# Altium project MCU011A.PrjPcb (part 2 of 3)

## Sheet MCU011A_EMCInputFilter.SchDoc: EMC Input Filter
size 431 x 279 mm; Date: Not shown in title block; ApprovedBy: Not shown in title block; CheckedBy: Not shown in title block; Author: Not shown in title block; CompanyName: Not shown in title block; Engineer: Not shown in title block; Organization: Not shown in title block; Address1: Not shown in title block; Address2: Not shown in title block; Address3: Not shown in title block; Address4: Not shown in title block; DocumentNumber: 1; Revision: Use project parameter SCH_Rev; SheetNumber: 2; SheetTotal: 10; PageSetup: Record=PageOptions¦CenterHorizontal=True¦CenterVertical=True¦PrintScale=1.00¦XCorrection=1.00¦YCorrection=1.00¦PrintKind=0¦BorderSize=5000000¦LeftOffset=0¦BottomOffset=0¦Orientation=2¦PaperLength=1000¦PaperWidth=1000¦Scale=100¦PaperSource=15¦PrintQuality=600¦MediaType=1¦DitherType=10¦PaperKind=Letter¦PrintScaleMode=1
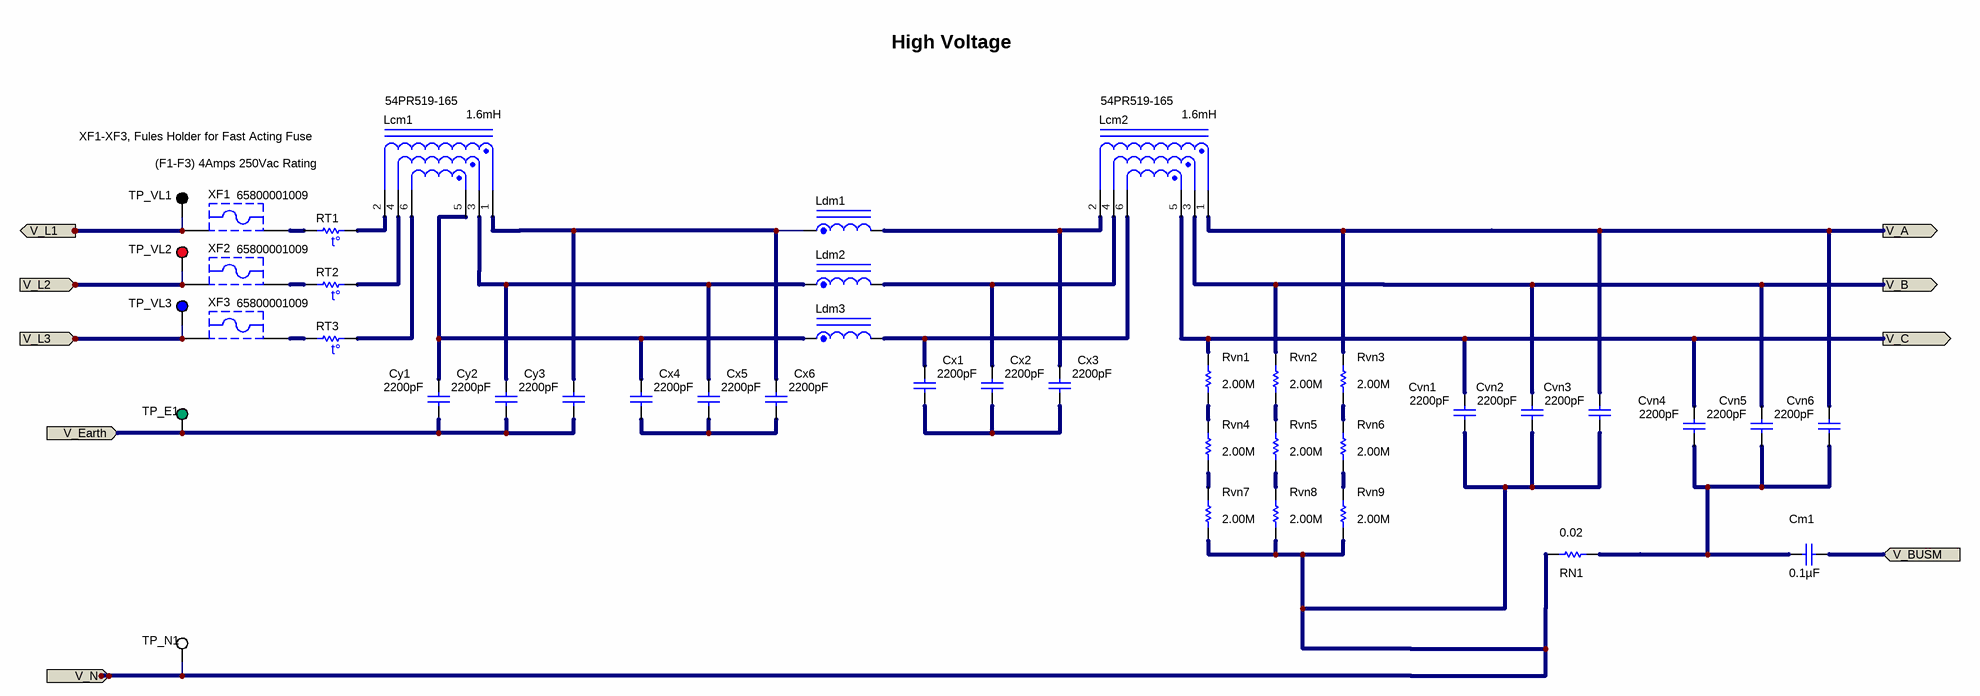
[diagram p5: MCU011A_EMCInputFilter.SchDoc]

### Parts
Cm1  ValueDisplayed: 0.1µF  [CAPRR1500W60L1750T550H1250]  (hidden comment: ECQ-U2A104ML)
Cvn1  ValueDisplayed: 2200pF  [2220_280]  (hidden comment: GA355QR7GF222KW01L)
Cvn2  ValueDisplayed: 2200pF  [2220_280]  (hidden comment: GA355QR7GF222KW01L)
Cvn3  ValueDisplayed: 2200pF  [2220_280]  (hidden comment: GA355QR7GF222KW01L)
Cvn4  ValueDisplayed: 2200pF  [2220_280]  (hidden comment: GA355QR7GF222KW01L)
Cvn5  ValueDisplayed: 2200pF  [2220_280]  (hidden comment: GA355QR7GF222KW01L)
Cvn6  ValueDisplayed: 2200pF  [2220_280]  (hidden comment: GA355QR7GF222KW01L)
Cx1  ValueDisplayed: 2200pF  [2220_280]  (hidden comment: GA355QR7GF222KW01L)
Cx2  ValueDisplayed: 2200pF  [2220_280]  (hidden comment: GA355QR7GF222KW01L)
Cx3  ValueDisplayed: 2200pF  [2220_280]  (hidden comment: GA355QR7GF222KW01L)
Cx4  ValueDisplayed: 2200pF  [2220_280]  (hidden comment: GA355QR7GF222KW01L)
Cx5  ValueDisplayed: 2200pF  [2220_280]  (hidden comment: GA355QR7GF222KW01L)
Cx6  ValueDisplayed: 2200pF  [2220_280]  (hidden comment: GA355QR7GF222KW01L)
Cy1  ValueDisplayed: 2200pF  [2220_280]  (hidden comment: GA355QR7GF222KW01L)
Cy2  ValueDisplayed: 2200pF  [2220_280]  (hidden comment: GA355QR7GF222KW01L)
Cy3  ValueDisplayed: 2200pF  [2220_280]  (hidden comment: GA355QR7GF222KW01L)
Lcm1  54PR519-165  ValueDisplayed: 1.6mH  [54PR519]
Lcm2  54PR519-165  ValueDisplayed: 1.6mH  [54PR519]
Ldm1  PA0431LNL  [PA0431LNL]  (value not drawn)
Ldm2  PA0431LNL  [PA0431LNL]  (value not drawn)
Ldm3  PA0431LNL  [PA0431LNL]  (value not drawn)
RN1  ValueDisplayed: 0.02  [2512]  (hidden comment: CRA2512-FZ-R020ELF)
RT1  SL32 10015  [AMETHERM_SL32]  (value not drawn)
RT2  SL32 10015  [AMETHERM_SL32]  (value not drawn)
RT3  SL32 10015  [AMETHERM_SL32]  (value not drawn)
Rvn1  ValueDisplayed: 2.00M  [0805_HV]  (hidden comment: ERJ-6ENF2004V)
Rvn2  ValueDisplayed: 2.00M  [0805_HV]  (hidden comment: ERJ-6ENF2004V)
Rvn3  ValueDisplayed: 2.00M  [0805_HV]  (hidden comment: ERJ-6ENF2004V)
Rvn4  ValueDisplayed: 2.00M  [0805_HV]  (hidden comment: ERJ-6ENF2004V)
Rvn5  ValueDisplayed: 2.00M  [0805_HV]  (hidden comment: ERJ-6ENF2004V)
Rvn6  ValueDisplayed: 2.00M  [0805_HV]  (hidden comment: ERJ-6ENF2004V)
Rvn7  ValueDisplayed: 2.00M  [0805_HV]  (hidden comment: ERJ-6ENF2004V)
Rvn8  ValueDisplayed: 2.00M  [0805_HV]  (hidden comment: ERJ-6ENF2004V)
Rvn9  ValueDisplayed: 2.00M  [0805_HV]  (hidden comment: ERJ-6ENF2004V)
TP_E1  5126  [Keystone5126]  (value not drawn)
TP_N1  5012  [Keystone5012]  (value not drawn)
TP_VL1  5011  [Keystone5011]  (value not drawn)
TP_VL2  5010  [Keystone5010]  (value not drawn)
TP_VL3  5127  [Keystone5127]  (value not drawn)
XF1  65800001009  [FuseHolder_65800001009]
XF2  65800001009  [FuseHolder_65800001009]
XF3  65800001009  [FuseHolder_65800001009]

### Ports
V_A (out), V_B (out), V_BUSM, V_C (out), V_Earth (in), V_L1 (in), V_L2 (in), V_L3 (in), V_N (in)

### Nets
V_A: Cvn3.1 Cvn6.1 Lcm2.1 Rvn3.2 ; port V_A
V_B: Cvn2.1 Cvn5.1 Lcm2.3 Rvn2.2 ; port V_B
V_C: Cvn1.1 Cvn4.1 Lcm2.5 Rvn1.2 ; port V_C
V_Earth: Cy1.2 Cy2.2 Cy3.2 TP_E1.1 ; port V_Earth
V_L1: TP_VL1.1 XF1.2 ; port V_L1
V_L2: TP_VL2.1 XF2.2 ; port V_L2
V_L3: TP_VL3.1 XF3.2 ; port V_L3
V_M: Cm1.2 ; port V_BUSM
V_N_Meas: Cvn1.2 Cvn2.2 Cvn3.2 RN1.1 Rvn7.1 Rvn8.1 Rvn9.1 TP_N1.1 ; port V_N
NetCm1_1: Cm1.1 Cvn4.2 Cvn5.2 Cvn6.2 RN1.2
NetCx1_1: Cx1.1 Lcm2.6 Ldm3.2
NetCx1_2: Cx1.2 Cx2.2 Cx3.2
NetCx2_1: Cx2.1 Lcm2.4 Ldm2.2
NetCx3_1: Cx3.1 Lcm2.2 Ldm1.2
NetCx4_1: Cx4.1 Cy1.1 Lcm1.5 Ldm3.1
NetCx4_2: Cx4.2 Cx5.2 Cx6.2
NetCx5_1: Cx5.1 Cy2.1 Lcm1.3 Ldm2.1
NetCx6_1: Cx6.1 Cy3.1 Lcm1.1 Ldm1.1
NetLcm1_2: Lcm1.2 RT1.2
NetLcm1_4: Lcm1.4 RT2.2
NetLcm1_6: Lcm1.6 RT3.2
NetRT1_1: RT1.1 XF1.1
NetRT2_1: RT2.1 XF2.1
NetRT3_1: RT3.1 XF3.1
NetRvn1_1: Rvn1.1 Rvn4.2
NetRvn2_1: Rvn2.1 Rvn5.2
NetRvn3_1: Rvn3.1 Rvn6.2
NetRvn4_1: Rvn4.1 Rvn7.2
NetRvn5_1: Rvn5.1 Rvn8.2
NetRvn6_1: Rvn6.1 Rvn9.2

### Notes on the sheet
- High Voltage
- XF1-XF3, Fules Holder for Fast Acting Fuse
- (near TP_VL1) (F1-F3) 4Amps 250Vac Rating

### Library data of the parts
Cm1 = ECQ-U2A104ML: CAP, Film, 0.1 µF, 275 V, +/- 20%, TH; Manufacturer: Panasonic; Polarized: N; CompType: Capacitor; Value: 0.1uF; U/M: EA; Cap_F: 0.0000001; Tolerance_%: 20; Value1: Unknown; VDC_V: 275; Value2: 275V; TaMin_C: -40; TaMax_C: 100; Cap_Case: Radial 17.5x5.5x12.5; AEC Category: Q200
Cvn1-Cvn6 Cx1-Cx6 Cy1-Cy3 = GA355QR7GF222KW01L: CAP, CERM, 2200 pF, 250 V, +/- 10%, X7R, 2220; Manufacturer: MuRata; Polarized: N; CompType: Capacitor; Value: 2200pF; U/M: EA; Cap_F: 0.0000000022; Tolerance_%: 10; Value1: Unknown; VDC_V: 250; Value2: 250V; TaMin_C: -55; TaMax_C: 125; Cap_Case: 2220; AEC Category: Q200
Lcm1 Lcm2 = 54PR519-165: Inductor, 1.6 mH, 0.008 ohm, TH; Manufacturer: Vitec Corporation; SymbolCreator: Altium; Ind_H: 1.6E-3; Value: 1.6mH; DCR_ohm: 0.008; Value2: A; SizeAreaWB_mm2: 2400.0201; SizeArea_mm2: 2208.0601; SizeX_mm: 46.99; SizeZ_mm: 21.59; AEC Category: Q200; AEC Qualified: N
Ldm1-Ldm3 = PA0431LNL: Inductor, Toroid, 20.5 A, 0.0055 ohm, TH; Manufacturer: Pulse Engineering; SymbolCreator: a0412235; Imax_A: 20.5; Irms: 20.5A @ 40C rise; DCR_ohm: 0.0055; Value2: 20.5A; AEC Category: Q200
RN1 = CRA2512-FZ-R020ELF: RES, 0.02, 1%, 3 W, 2512; Manufacturer: Bourns; CompType: Resistor; Value: 0.02; Value_Code: R020; Tolerance_%: 1; Power_W: 3; Value2: 3W; TempCo: 75 ppm/C; EIA_Code: E96; U/M: EA; AEC Category: Q200
RT1-RT3 = SL32 10015: ICL, 10OHM, 20%, 15A, TH; Manufacturer: Ametherm
Rvn1-Rvn9 = ERJ-6ENF2004V: RES, 2.00 M, 1%, 0.125 W, AEC-Q200 Grade 0, 0805; Manufacturer: Panasonic; CompType: Resistor; Value: 2.00Meg; Res_ohm: 2000000; Value_Code: 2M00; Tolerance_%: 1; Power_W: 0.125; Value2: 0.125W; VDC_V: 150; TempCo: 100 ppm/C; EIA_Code: E96; U/M: EA; AEC Category: Q200; AEC Qualified: Y; AEC Grade: 0
TP_E1 = 5126: Test Point, Multipurpose, Green, TH; Manufacturer: Keystone; SymbolCreator: a0412235; CompType: Test Point Loop; ContactFinish: Silver
TP_N1 = 5012: Test Point, Multipurpose, White, TH; Manufacturer: Keystone; CompType: Test Point Loop; ContactFinish: Silver
TP_VL1 = 5011: Test Point, Multipurpose, Black, TH; Manufacturer: Keystone; CompType: Test Point Loop; ContactFinish: Silver
TP_VL2 = 5010: Test Point, Multipurpose, Red, TH; Manufacturer: Keystone; CompType: Test Point Loop; ContactFinish: Silver
TP_VL3 = 5127: Test Point, Multipurpose, Blue, TH; Manufacturer: Keystone; CompType: Test Point Loop; U/M: EA; ContactFinish: Silver
XF1-XF3 = 65800001009: FuseHolder for 5x20mm Fuses, SMT; Manufacturer: Littelfuse; SymbolCreator: a0412235

## Sheet MCU011A_SensingInductorCurrent.SchDoc: Inductor Current Sensing Interface Circuit
size 431 x 279 mm; Date: Not shown in title block; ApprovedBy: Not shown in title block; CheckedBy: Not shown in title block; Author: Not shown in title block; CompanyName: Not shown in title block; DrawnBy: Manish Bhardwaj; Engineer: Not shown in title block; Organization: Not shown in title block; Address1: Not shown in title block; Address2: Not shown in title block; Address3: Not shown in title block; Address4: Not shown in title block; DocumentNumber: 1; Revision: Use project parameter SCH_Rev; SheetNumber: 6; SheetTotal: 10; PageSetup: Record=PageOptions¦CenterHorizontal=True¦CenterVertical=True¦PrintScale=1.00¦XCorrection=1.00¦YCorrection=1.00¦PrintKind=0¦BorderSize=5000000¦LeftOffset=0¦BottomOffset=0¦Orientation=2¦PaperLength=1000¦PaperWidth=1000¦Scale=100¦PaperSource=15¦PrintQuality=600¦MediaType=1¦DitherType=10¦PaperKind=Letter¦PrintScaleMode=1
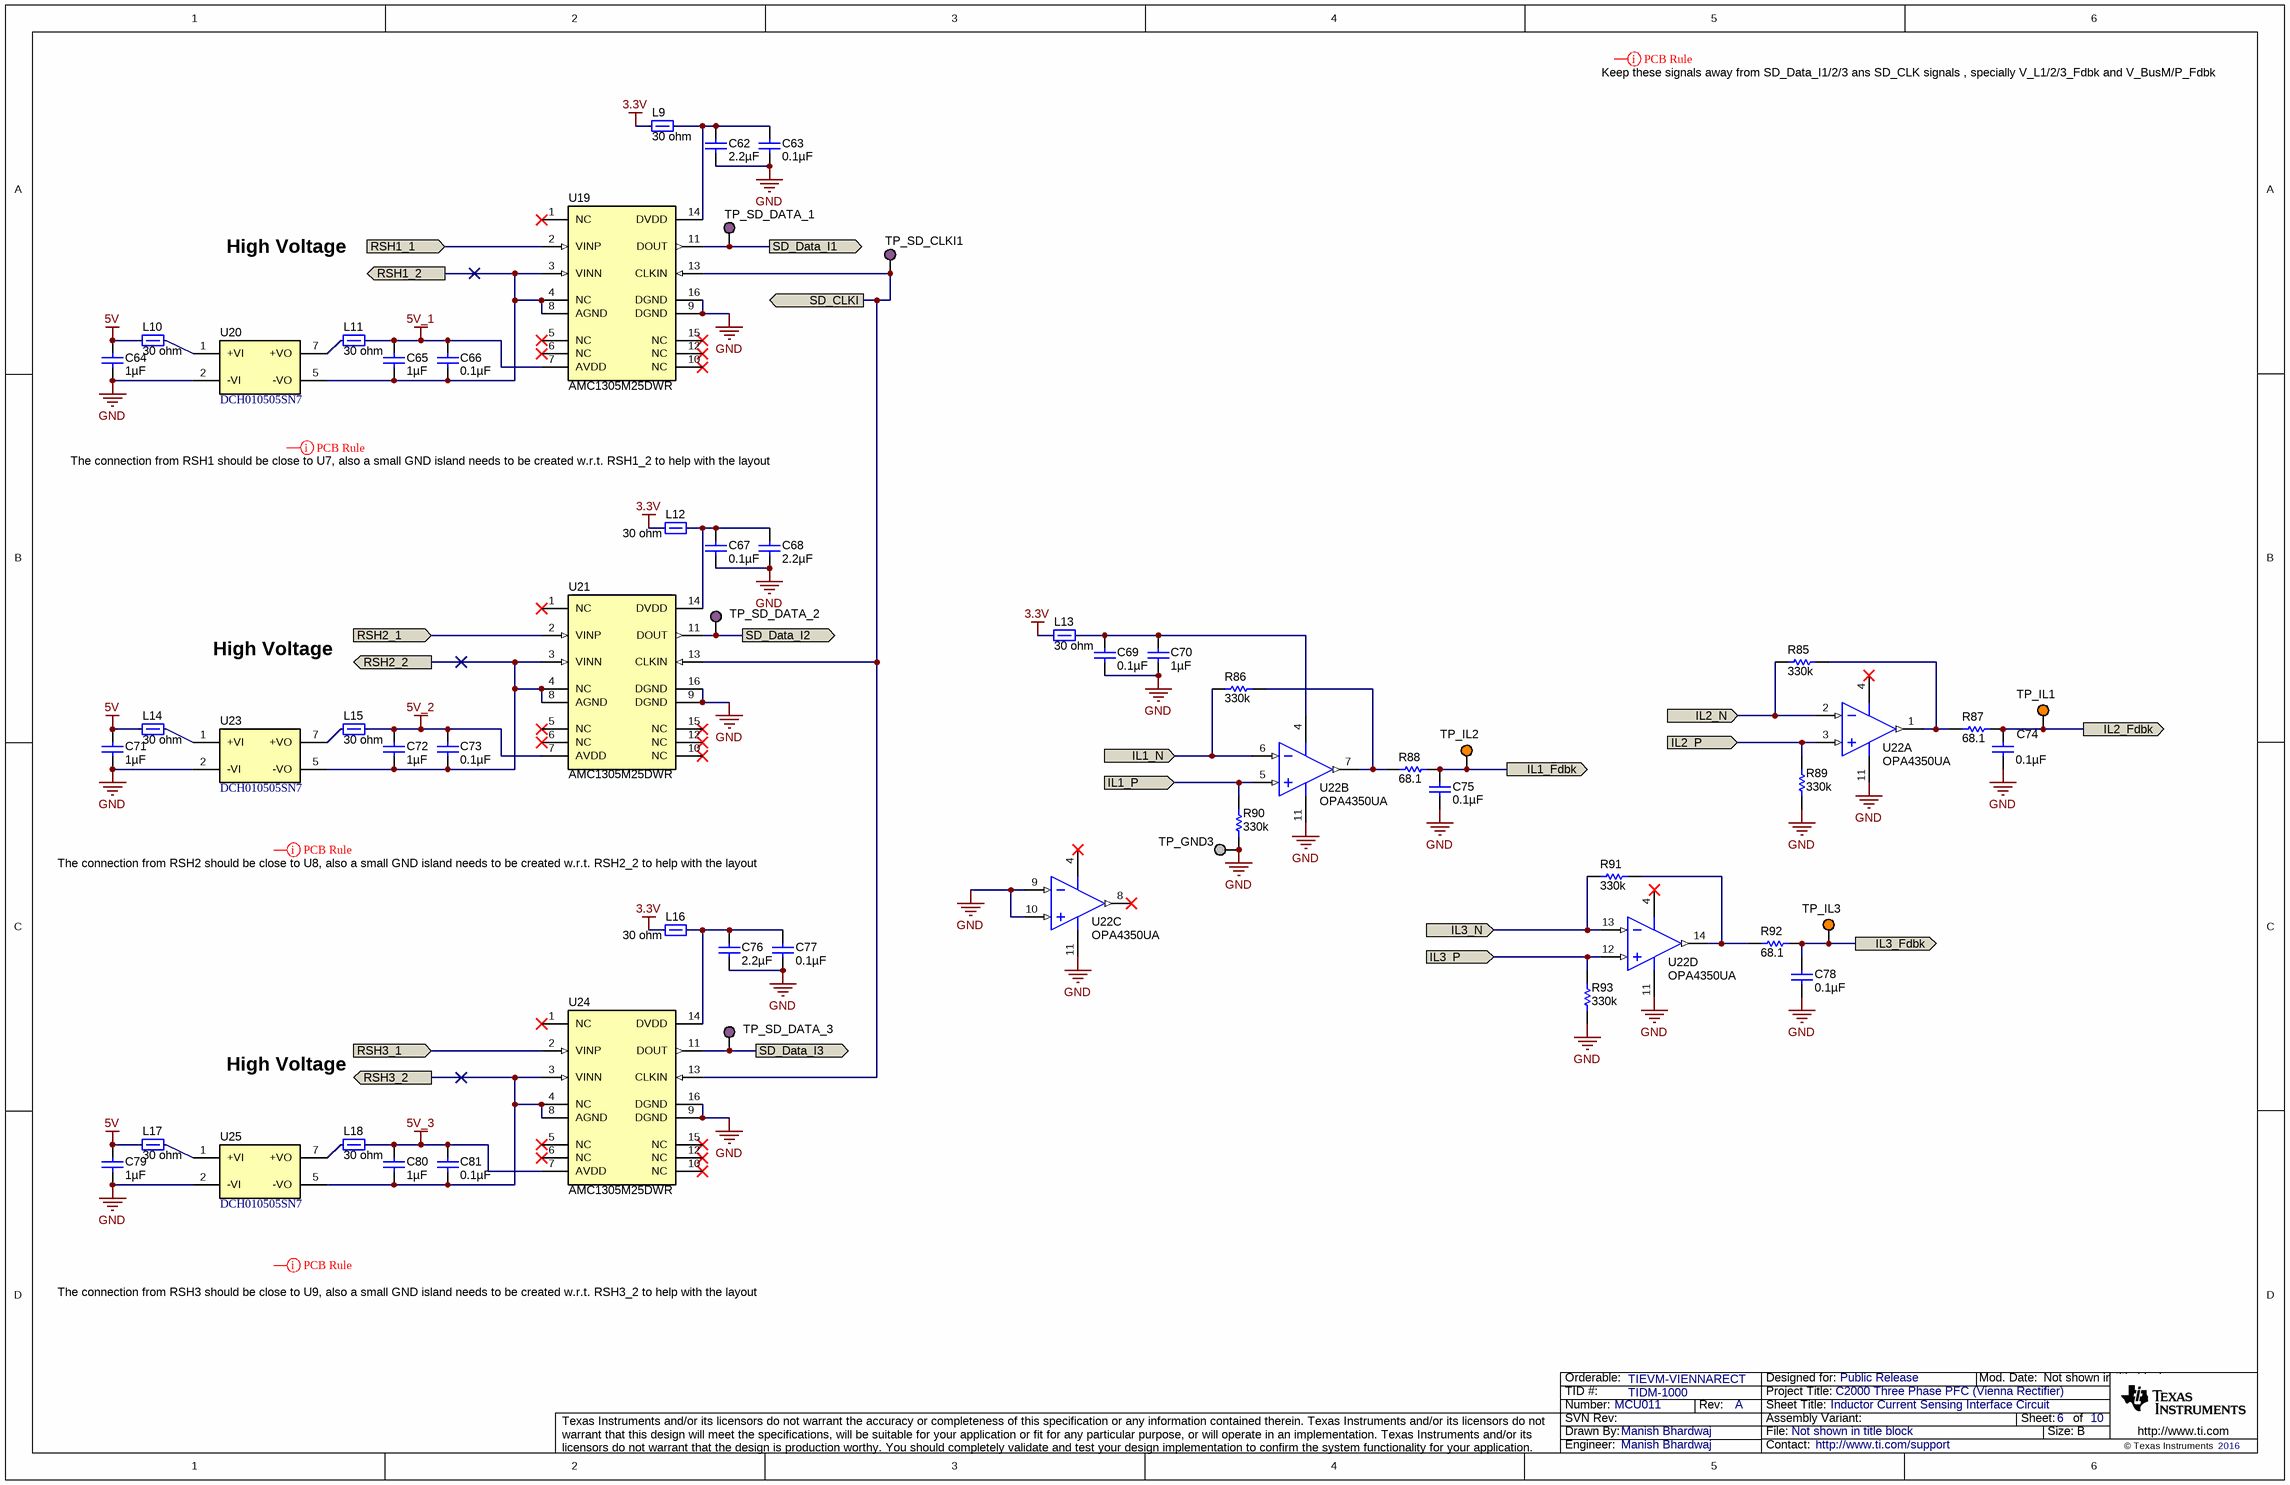
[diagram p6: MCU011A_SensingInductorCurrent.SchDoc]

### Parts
C62  ValueDisplayed: 2.2µF  [0805_HV]  (hidden comment: 0805YD225KAT2A)
C63  ValueDisplayed: 0.1µF  [0805]  (hidden comment: C0805C104K3RACTU)
C64  ValueDisplayed: 1µF  [0805]  (hidden comment: GRM21BR71H105KA12L)
C65  ValueDisplayed: 1µF  [0805]  (hidden comment: GRM21BR71H105KA12L)
C66  ValueDisplayed: 0.1µF  [0805]  (hidden comment: C0805C104K3RACTU)
C67  ValueDisplayed: 0.1µF  [0805]  (hidden comment: C0805C104K3RACTU)
C68  ValueDisplayed: 2.2µF  [0805_HV]  (hidden comment: 0805YD225KAT2A)
C69  ValueDisplayed: 0.1µF  [0603]  (hidden comment: 0603YC104JAT2A)
C70  ValueDisplayed: 1µF  [0603]  (hidden comment: C0603C105K3RACTU)
C71  ValueDisplayed: 1µF  [0805]  (hidden comment: GRM21BR71H105KA12L)
C72  ValueDisplayed: 1µF  [0805]  (hidden comment: GRM21BR71H105KA12L)
C73  ValueDisplayed: 0.1µF  [0805]  (hidden comment: C0805C104K3RACTU)
C74  ValueDisplayed: 0.1µF  [0603]  (hidden comment: 0603YC104JAT2A)
C75  ValueDisplayed: 0.1µF  [0603]  (hidden comment: 0603YC104JAT2A)
C76  ValueDisplayed: 2.2µF  [0805_HV]  (hidden comment: 0805YD225KAT2A)
C77  ValueDisplayed: 0.1µF  [0805]  (hidden comment: C0805C104K3RACTU)
C78  ValueDisplayed: 0.1µF  [0603]  (hidden comment: 0603YC104JAT2A)
C79  ValueDisplayed: 1µF  [0805]  (hidden comment: GRM21BR71H105KA12L)
C80  ValueDisplayed: 1µF  [0805]  (hidden comment: GRM21BR71H105KA12L)
C81  ValueDisplayed: 0.1µF  [0805]  (hidden comment: C0805C104K3RACTU)
L9  value 30 ohm  [0805]  (hidden comment: MPZ2012S300AT000)
L10  value 30 ohm  [0805]  (hidden comment: MPZ2012S300AT000)
L11  value 30 ohm  [0805]  (hidden comment: MPZ2012S300AT000)
L12  value 30 ohm  [0805]  (hidden comment: MPZ2012S300AT000)
L13  value 30 ohm  [0805]  (hidden comment: MPZ2012S300AT000)
L14  value 30 ohm  [0805]  (hidden comment: MPZ2012S300AT000)
L15  value 30 ohm  [0805]  (hidden comment: MPZ2012S300AT000)
L16  value 30 ohm  [0805]  (hidden comment: MPZ2012S300AT000)
L17  value 30 ohm  [0805]  (hidden comment: MPZ2012S300AT000)
L18  value 30 ohm  [0805]  (hidden comment: MPZ2012S300AT000)
R85  ValueDisplayed: 330k  [0603]  (hidden comment: ERJ-3EKF3303V)
R86  ValueDisplayed: 330k  [0603]  (hidden comment: ERJ-3EKF3303V)
R87  ValueDisplayed: 68.1  [0603]  (hidden comment: CRCW060368R1FKEA)
R88  ValueDisplayed: 68.1  [0603]  (hidden comment: CRCW060368R1FKEA)
R89  ValueDisplayed: 330k  [0603]  (hidden comment: ERJ-3EKF3303V)
R90  ValueDisplayed: 330k  [0603]  (hidden comment: ERJ-3EKF3303V)
R91  ValueDisplayed: 330k  [0603]  (hidden comment: ERJ-3EKF3303V)
R92  ValueDisplayed: 68.1  [0603]  (hidden comment: CRCW060368R1FKEA)
R93  ValueDisplayed: 330k  [0603]  (hidden comment: ERJ-3EKF3303V)
TP_GND3  5128  [Keystone5128]  (value not drawn)
TP_IL1  5013  [Keystone5013]  (value not drawn)
TP_IL2  5013  [Keystone5013]  (value not drawn)
TP_IL3  5013  [Keystone5013]  (value not drawn)
TP_SD_CLKI1  5129  [Keystone5129]  (value not drawn)
TP_SD_DATA_1  5129  [Keystone5129]  (value not drawn)
TP_SD_DATA_2  5129  [Keystone5129]  (value not drawn)
TP_SD_DATA_3  5129  [Keystone5129]  (value not drawn)
U19  AMC1305M25DWR  [DW0016B_N]
U20  DCH010505SN7  [EDJ0004A]
U21  AMC1305M25DWR  [DW0016B_N]
U22  OPA4350UA  [D0014A_N]  (parts A,B,C,D of 4)
U23  DCH010505SN7  [EDJ0004A]
U24  AMC1305M25DWR  [DW0016B_N]
U25  DCH010505SN7  [EDJ0004A]

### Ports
IL1_Fdbk (out), IL1_N (in), IL1_P (in), IL2_Fdbk (out), IL2_N (in), IL2_P (in), IL3_Fdbk (out), IL3_N (in), IL3_P (in), RSH1_1 (in), RSH1_2, RSH2_1 (in), RSH2_2, RSH3_1 (in), RSH3_2, SD_CLKI (out), SD_Data_I1 (out), SD_Data_I2 (out), SD_Data_I3 (out)

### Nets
3.3V: L9.2 L12.2 L13.2 L16.2
5V: C64.1 C71.1 C79.1 L10.1 L14.1 L17.1
5V_1: C65.1 C66.1 L11.2 U19.7(AVDD)
5V_2: C72.1 C73.1 L15.2 U21.7(AVDD)
5V_3: C80.1 C81.1 L18.2 U24.7(AVDD)
GND: C62.2 C63.1 C64.2 C67.1 C68.2 C69.1 C70.2 C71.2 C74.1 C75.1 C76.2 C77.1 C78.1 C79.2 R89.1 R90.1 R93.1 TP_GND3.1 U19.9(DGND) U19.16(DGND) U20.2(-VI) U21.9(DGND) U21.16(DGND) U22.9(IN_C-) U22.10(IN_C+) U22.11(V-) U23.2(-VI) U24.9(DGND) U24.16(DGND) U25.2(-VI)
IL1_Fdbk: C75.2 R88.2 TP_IL2.1 ; port IL1_Fdbk
IL1_N: R86.1 U22.6(IN_B-) ; port IL1_N
IL1_P: R90.2 U22.5(IN_B+) ; port IL1_P
IL2_Fdbk: C74.2 R87.2 TP_IL1.1 ; port IL2_Fdbk
IL2_N: R85.1 U22.2(IN_A-) ; port IL2_N
IL2_P: R89.2 U22.3(IN_A+) ; port IL2_P
IL3_Fdbk: C78.2 R92.1 TP_IL3.1 ; port IL3_Fdbk
IL3_N: R91.1 U22.13(IN_D-) ; port IL3_N
IL3_P: R93.2 U22.12(IN_D+) ; port IL3_P
RSH1_1: U19.2(VINP) ; port RSH1_1
RSH1_2: C65.2 C66.2 U19.3(VINN) U19.4(NC) U19.8(AGND) U20.5(-VO) ; port RSH1_2
RSH2_1: U21.2(VINP) ; port RSH2_1
RSH2_2: C72.2 C73.2 U21.3(VINN) U21.4(NC) U21.8(AGND) U23.5(-VO) ; port RSH2_2
RSH3_1: U24.2(VINP) ; port RSH3_1
RSH3_2: C80.2 C81.2 U24.3(VINN) U24.4(NC) U24.8(AGND) U25.5(-VO) ; port RSH3_2
SD_CLKI: TP_SD_CLKI1.1 U19.13(CLKIN) U21.13(CLKIN) U24.13(CLKIN) ; port SD_CLKI
SD_Data_I1: TP_SD_DATA_1.1 U19.11(DOUT) ; port SD_Data_I1
SD_Data_I2: TP_SD_DATA_2.1 U21.11(DOUT) ; port SD_Data_I2
SD_Data_I3: TP_SD_DATA_3.1 U24.11(DOUT) ; port SD_Data_I3
NetC62_1: C62.1 C63.2 L9.1 U19.14(DVDD)
NetC67_2: C67.2 C68.1 L12.1 U21.14(DVDD)
NetC69_2: C69.2 C70.1 L13.1 U22.4(V+)
NetC76_1: C76.1 C77.2 L16.1 U24.14(DVDD)
NetL10_2: L10.2 U20.1(+VI)
NetL11_1: L11.1 U20.7(+VO)
NetL14_2: L14.2 U23.1(+VI)
NetL15_1: L15.1 U23.7(+VO)
NetL17_2: L17.2 U25.1(+VI)
NetL18_1: L18.1 U25.7(+VO)
NetR85_2: R85.2 R87.1 U22.1(OUT_A)
NetR86_2: R86.2 R88.1 U22.7(OUT_B)
NetR91_2: R91.2 R92.2 U22.14(OUT_D)

Not connected (* = marked no-connect by the designer): U19 1(NC)* 5(NC)* 6(NC)* 10(NC)* 12(NC)* 15(NC)*; U21 1(NC)* 5(NC)* 6(NC)* 10(NC)* 12(NC)* 15(NC)*; U22 8(OUT_C)*; U24 1(NC)* 5(NC)* 6(NC)* 10(NC)* 12(NC)* 15(NC)*

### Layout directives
rule Undefined: (no net found under the mark)

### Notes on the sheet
- Keep these signals away from SD_Data_I1/2/3 ans SD_CLK signals , specially V_L1/2/3_Fdbk and V_BusM/P_Fdbk
- High Voltage
- The connection from RSH1 should be close to U7, also a small GND island needs to be created w.r.t. RSH1_2 to help with the layout
- The connection from RSH2 should be close to U8, also a small GND island needs to be created w.r.t. RSH2_2 to help with the layout
- The connection from RSH3 should be close to U9, also a small GND island needs to be created w.r.t. RSH3_2 to help with the layout

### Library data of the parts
C62 C68 C76 = 0805YD225KAT2A: CAP, CERM, 2.2 µF, 16 V, +/- 10%, X5R, 0805; Manufacturer: AVX; Polarized: N; CompType: Capacitor; Value: 2.2uF; U/M: EA; Cap_F: 0.0000022; Tolerance_%: 10; ESR_ohm: 0.009; Value1: 0.009 ohm; VDC_V: 16; Value2: 16V; TaMin_C: -55; TaMax_C: 85; Cap_Case: 0805; AEC Category: Q200
C63 C66 C67 C73 C77 C81 = C0805C104K3RACTU: CAP, CERM, 0.1 µF, 25 V, +/- 10%, X7R, 0805; Manufacturer: Kemet; Polarized: N; CompType: Capacitor; Value: 0.1uF; U/M: EA; Cap_F: 0.0000001; Tolerance_%: 10; ESR_ohm: 0.064; Value1: 0.064 ohm; VDC_V: 25; Value2: 25V; IRMS_A: 1.64; TaMin_C: -55; TaMax_C: 125; AEC Category: Q200
C64 C65 C71 C72 C79 C80 = GRM21BR71H105KA12L: CAP, CERM, 1 µF, 50 V, +/- 10%, X7R, 0805; Manufacturer: MuRata; Polarized: N; CompType: Capacitor; Value: 1uF; U/M: EA; Cap_F: 0.000001; Tolerance_%: 10; Value1: Unknown; VDC_V: 50; Value2: 50V; TaMin_C: -55; TaMax_C: 125; AEC Category: Q200
C69 C74 C75 C78 = 0603YC104JAT2A: CAP, CERM, 0.1 µF, 16 V, +/- 5%, X7R, 0603; Manufacturer: AVX; Polarized: N; CompType: Capacitor; Value: 0.1uF; U/M: EA; Cap_F: 0.0000001; Tolerance_%: 5; ESR_ohm: 0.039; Value1: 0.039 ohm; VDC_V: 16; Value2: 16V; TaMin_C: -55; TaMax_C: 125; SizeArea_mm2: 1.28; SizeAreaWB_mm2: 4.68; SizeX_mm: 1.6; SizeY_mm: 0.8; SizeZ_mm: 1; AEC Category: Q200
C70 = C0603C105K3RACTU: CAP, CERM, 1 µF, 25 V, +/- 10%, X7R, 0603; Manufacturer: Kemet; Polarized: N; CompType: Capacitor; Value: 1uF; U/M: EA; Cap_F: 0.000001; Tolerance_%: 10; Value1: Unknown; VDC_V: 25; Value2: 25V; TaMin_C: -55; TaMax_C: 125; SizeArea_mm2: 1.28; SizeAreaWB_mm2: 4.68; SizeX_mm: 1.6; SizeY_mm: 0.8; SizeZ_mm: 1; AEC Category: Q200
L9-L18 = MPZ2012S300AT000: Ferrite Bead, 30 ohm @ 100 MHz, 6 A, 0805; Manufacturer: TDK; Imax_A: 6; DCR_ohm: 0.01; Value1: 0.01 ohm; Value2: 6A; ZTyp@100MHz_Ohm: 30
R85 R86 R89-R91 R93 = ERJ-3EKF3303V: RES, 330 k, 1%, 0.1 W, AEC-Q200 Grade 0, 0603; Manufacturer: Panasonic; CompType: Resistor; Value: 330k; Res_ohm: 330000; Tolerance_%: 1; Power_W: 0.1; Value2: 0.1W; VDC_V: 75; TempCo: 100 ppm/C; SizeArea_mm2: 1.28; SizeX_mm: 1.6; SizeY_mm: 0.8; U/M: EA; AEC Category: Q200; AEC Qualified: Y; AEC Grade: 0
R87 R88 R92 = CRCW060368R1FKEA: RES, 68.1, 1%, 0.1 W, 0603; Manufacturer: Vishay-Dale; CompType: Resistor; Value: 68.1; Value_Code: 68R1; Tolerance_%: 1; Power_W: 0.1; Value2: 0.1W; VDC_V: 75; TempCo: 100 ppm/C; SizeArea_mm2: 1.28; SizeX_mm: 1.6; SizeY_mm: 0.8; EIA_Code: E96; U/M: EA; AEC Category: Q200
TP_GND3 = 5128: Test Point, Multipurpose, Grey, TH; Manufacturer: Keystone; SymbolCreator: a0412235; CompType: Test Point Loop; ContactFinish: Silver
TP_IL1-TP_IL3 = 5013: Test Point, Multipurpose, Orange, TH; Manufacturer: Keystone; CompType: Test Point Loop; ContactFinish: Silver
TP_SD_CLKI1 TP_SD_DATA_1-TP_SD_DATA_3 = 5129: Test Point, Multipurpose, Purple, TH; Manufacturer: Keystone; SymbolCreator: a0412235; CompType: Test Point Loop; ContactFinish: Silver
U19 U21 U24 = AMC1305M25DWR: Reinforced Isolated Modulator with ±250mV Input and CMOS Interface, DW0016B (SOIC-16); Manufacturer: Texas Instruments; SymbolCreator: a0411947; SizeArea_mm2: 107.12; SizeAreaWB_mm2: 152.52; SizeX_mm: 10.4; SizeY_mm: 10.3; SizeZ_mm: 2.65; CompType: IC; U/M: EA
U20 U23 U25 = DCH010505SN7: Miniature, 1 W, 3 kVDC Isolated DC-DC Converter, -40 to 85 degC, 4-pin Module (EDJ4), Pb-Free (RoHS); Manufacturer: Texas Instruments; Alternate PartNumber: Equivalent; Iout(Max)(A): 0.2; Regulated Outputs(#): 1; SubFamily: 1 W & 2 W Miniature; Vin(Max)(V): 5.5; Vin(Min)(V): 4.5
U22 = OPA4350UA: High-Speed, Single-Supply, Rail-to-Rail Operational Amplifier MicroAmplifier(TM) Series, 2.7 to 5.5 V, -55 to 150 degC, 14-pin SOIC (D0014A), Green (RoHS & no Sb/Br); Manufacturer: Texas Instruments; Alternate PartNumber: Equivalent; CMRR(Min)(dB): 66; IIB(Max)(pA): 10; Iq per channel(Max)(mA): 7.5; Number of Channels: 4; Slew Rate(Typ)(V/us): 22; Sub Family: Low Input Bias Current Amp (<=10pA), Low Offset Voltage Amplifier (<=500uV), Low Supply Voltage Amplifier (<=2.7V), Precision Amplifier; Total Supply Voltage(Max)(+5V is 5, +/-5V is 10): 5.5; Total Supply Voltage(Min)(+5V is 5, +/-5V is 10): 2.7; Vio (25C)(Max)(mV): 0.5; Vn at 1kHz(Typ)(nV/rtHz): 18

## Sheet MCU011A_SensingInputVoltage.SchDoc: Input AC Voltage Sensing Interface Circuitry
size 431 x 279 mm; Date: Not shown in title block; ApprovedBy: Not shown in title block; CheckedBy: Not shown in title block; Author: Not shown in title block; CompanyName: Not shown in title block; DrawnBy: Manish Bhardwaj; Engineer: Not shown in title block; Organization: Not shown in title block; Address1: Not shown in title block; Address2: Not shown in title block; Address3: Not shown in title block; Address4: Not shown in title block; DocumentNumber: 1; Revision: Use project parameter SCH_Rev; SheetNumber: 5; SheetTotal: 10; PageSetup: Record=PageOptions¦CenterHorizontal=True¦CenterVertical=True¦PrintScale=1.00¦XCorrection=1.00¦YCorrection=1.00¦PrintKind=0¦BorderSize=5000000¦LeftOffset=0¦BottomOffset=0¦Orientation=2¦PaperLength=1000¦PaperWidth=1000¦Scale=100¦PaperSource=15¦PrintQuality=600¦MediaType=1¦DitherType=10¦PaperKind=Letter¦PrintScaleMode=1
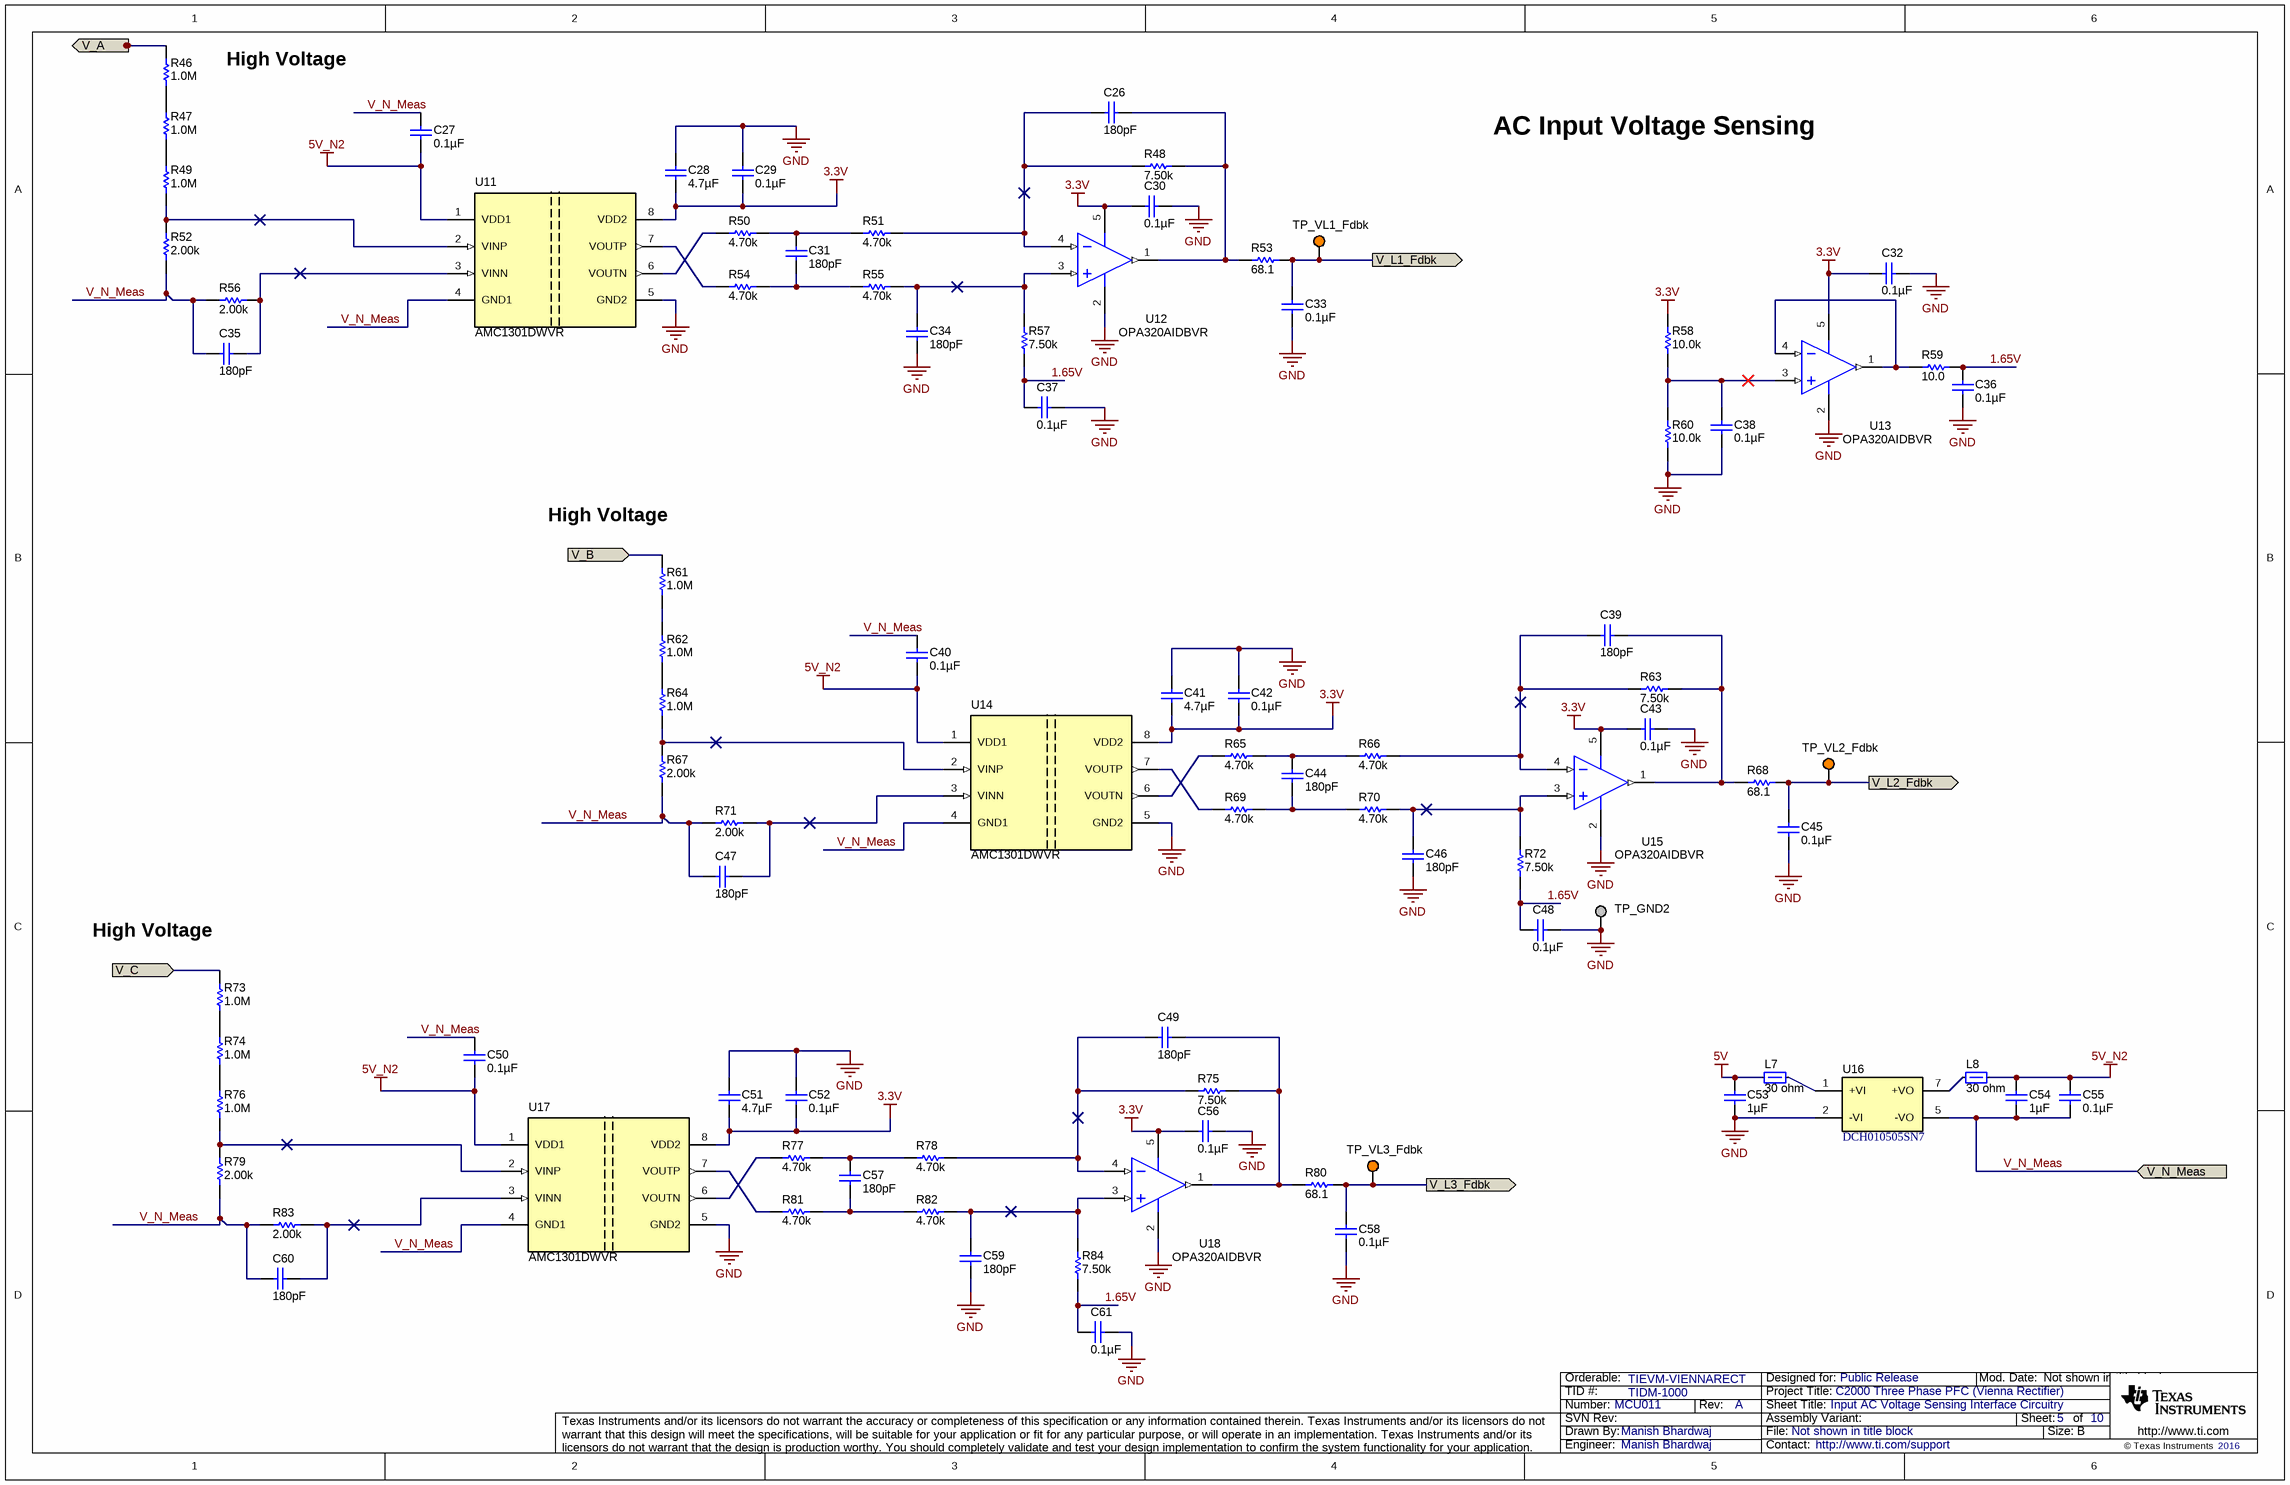
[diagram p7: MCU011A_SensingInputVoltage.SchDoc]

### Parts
C26  ValueDisplayed: 180pF  [0603]  (hidden comment: C0603C181J5GACTU)
C27  ValueDisplayed: 0.1µF  [0603]  (hidden comment: 0603YC104JAT2A)
C28  ValueDisplayed: 4.7µF  [0805]  (hidden comment: C2012X5R1H475K125AB)
C29  ValueDisplayed: 0.1µF  [0603]  (hidden comment: 0603YC104JAT2A)
C30  ValueDisplayed: 0.1µF  [0603]  (hidden comment: 0603YC104JAT2A)
C31  ValueDisplayed: 180pF  [0603]  (hidden comment: C0603C181J5GACTU)
C32  ValueDisplayed: 0.1µF  [0603]  (hidden comment: 0603YC104JAT2A)
C33  ValueDisplayed: 0.1µF  [0603]  (hidden comment: 0603YC104JAT2A)
C34  ValueDisplayed: 180pF  [0603]  (hidden comment: C0603C181J5GACTU)
C35  ValueDisplayed: 180pF  [0603]  (hidden comment: C0603C181J5GACTU)
C36  ValueDisplayed: 0.1µF  [0603]  (hidden comment: 0603YC104JAT2A)
C37  ValueDisplayed: 0.1µF  [0603]  (hidden comment: 0603YC104JAT2A)
C38  ValueDisplayed: 0.1µF  [0603]  (hidden comment: 0603YC104JAT2A)
C39  ValueDisplayed: 180pF  [0603]  (hidden comment: C0603C181J5GACTU)
C40  ValueDisplayed: 0.1µF  [0603]  (hidden comment: 0603YC104JAT2A)
C41  ValueDisplayed: 4.7µF  [0805]  (hidden comment: C2012X5R1H475K125AB)
C42  ValueDisplayed: 0.1µF  [0603]  (hidden comment: 0603YC104JAT2A)
C43  ValueDisplayed: 0.1µF  [0603]  (hidden comment: 0603YC104JAT2A)
C44  ValueDisplayed: 180pF  [0603]  (hidden comment: C0603C181J5GACTU)
C45  ValueDisplayed: 0.1µF  [0603]  (hidden comment: 0603YC104JAT2A)
C46  ValueDisplayed: 180pF  [0603]  (hidden comment: C0603C181J5GACTU)
C47  ValueDisplayed: 180pF  [0603]  (hidden comment: C0603C181J5GACTU)
C48  ValueDisplayed: 0.1µF  [0603]  (hidden comment: 0603YC104JAT2A)
C49  ValueDisplayed: 180pF  [0603]  (hidden comment: C0603C181J5GACTU)
C50  ValueDisplayed: 0.1µF  [0603]  (hidden comment: 0603YC104JAT2A)
C51  ValueDisplayed: 4.7µF  [0805]  (hidden comment: C2012X5R1H475K125AB)
C52  ValueDisplayed: 0.1µF  [0603]  (hidden comment: 0603YC104JAT2A)
C53  ValueDisplayed: 1µF  [0805]  (hidden comment: GRM21BR71H105KA12L)
C54  ValueDisplayed: 1µF  [0805]  (hidden comment: GRM21BR71H105KA12L)
C55  ValueDisplayed: 0.1µF  [0805]  (hidden comment: C0805C104K3RACTU)
C56  ValueDisplayed: 0.1µF  [0603]  (hidden comment: 0603YC104JAT2A)
C57  ValueDisplayed: 180pF  [0603]  (hidden comment: C0603C181J5GACTU)
C58  ValueDisplayed: 0.1µF  [0603]  (hidden comment: 0603YC104JAT2A)
C59  ValueDisplayed: 180pF  [0603]  (hidden comment: C0603C181J5GACTU)
C60  ValueDisplayed: 180pF  [0603]  (hidden comment: C0603C181J5GACTU)
C61  ValueDisplayed: 0.1µF  [0603]  (hidden comment: 0603YC104JAT2A)
L7  value 30 ohm  [0805]  (hidden comment: MPZ2012S300AT000)
L8  value 30 ohm  [0805]  (hidden comment: MPZ2012S300AT000)
R46  ValueDisplayed: 1.0M  [0805_HV]  (hidden comment: CRCW08051M00JNEA)
R47  ValueDisplayed: 1.0M  [0805_HV]  (hidden comment: CRCW08051M00JNEA)
R48  ValueDisplayed: 7.50k  [0603]  (hidden comment: ERJ-3EKF7501V)
R49  ValueDisplayed: 1.0M  [0805_HV]  (hidden comment: CRCW08051M00JNEA)
R50  ValueDisplayed: 4.70k  [0603]  (hidden comment: RC0603FR-074K7L)
R51  ValueDisplayed: 4.70k  [0603]  (hidden comment: RC0603FR-074K7L)
R52  ValueDisplayed: 2.00k  [0603]  (hidden comment: CRCW06032K00FKEA)
R53  ValueDisplayed: 68.1  [0603]  (hidden comment: CRCW060368R1FKEA)
R54  ValueDisplayed: 4.70k  [0603]  (hidden comment: RC0603FR-074K7L)
R55  ValueDisplayed: 4.70k  [0603]  (hidden comment: RC0603FR-074K7L)
R56  ValueDisplayed: 2.00k  [0603]  (hidden comment: CRCW06032K00FKEA)
R57  ValueDisplayed: 7.50k  [0603]  (hidden comment: ERJ-3EKF7501V)
R58  ValueDisplayed: 10.0k  [0603]  (hidden comment: CRCW060310K0FKEA)
R59  ValueDisplayed: 10.0  [0603]  (hidden comment: CRCW060310R0FKEA)
R60  ValueDisplayed: 10.0k  [0603]  (hidden comment: CRCW060310K0FKEA)
R61  ValueDisplayed: 1.0M  [0805_HV]  (hidden comment: CRCW08051M00JNEA)
R62  ValueDisplayed: 1.0M  [0805_HV]  (hidden comment: CRCW08051M00JNEA)
R63  ValueDisplayed: 7.50k  [0603]  (hidden comment: ERJ-3EKF7501V)
R64  ValueDisplayed: 1.0M  [0805_HV]  (hidden comment: CRCW08051M00JNEA)
R65  ValueDisplayed: 4.70k  [0603]  (hidden comment: RC0603FR-074K7L)
R66  ValueDisplayed: 4.70k  [0603]  (hidden comment: RC0603FR-074K7L)
R67  ValueDisplayed: 2.00k  [0603]  (hidden comment: CRCW06032K00FKEA)
R68  ValueDisplayed: 68.1  [0603]  (hidden comment: CRCW060368R1FKEA)
R69  ValueDisplayed: 4.70k  [0603]  (hidden comment: RC0603FR-074K7L)
R70  ValueDisplayed: 4.70k  [0603]  (hidden comment: RC0603FR-074K7L)
R71  ValueDisplayed: 2.00k  [0603]  (hidden comment: CRCW06032K00FKEA)
R72  ValueDisplayed: 7.50k  [0603]  (hidden comment: ERJ-3EKF7501V)
R73  ValueDisplayed: 1.0M  [0805_HV]  (hidden comment: CRCW08051M00JNEA)
R74  ValueDisplayed: 1.0M  [0805_HV]  (hidden comment: CRCW08051M00JNEA)
R75  ValueDisplayed: 7.50k  [0603]  (hidden comment: ERJ-3EKF7501V)
R76  ValueDisplayed: 1.0M  [0805_HV]  (hidden comment: CRCW08051M00JNEA)
R77  ValueDisplayed: 4.70k  [0603]  (hidden comment: RC0603FR-074K7L)
R78  ValueDisplayed: 4.70k  [0603]  (hidden comment: RC0603FR-074K7L)
R79  ValueDisplayed: 2.00k  [0603]  (hidden comment: CRCW06032K00FKEA)
R80  ValueDisplayed: 68.1  [0603]  (hidden comment: CRCW060368R1FKEA)
R81  ValueDisplayed: 4.70k  [0603]  (hidden comment: RC0603FR-074K7L)
R82  ValueDisplayed: 4.70k  [0603]  (hidden comment: RC0603FR-074K7L)
R83  ValueDisplayed: 2.00k  [0603]  (hidden comment: CRCW06032K00FKEA)
R84  ValueDisplayed: 7.50k  [0603]  (hidden comment: ERJ-3EKF7501V)
TP_GND2  5128  [Keystone5128]  (value not drawn)
TP_VL1_Fdbk  5013  [Keystone5013]  (value not drawn)
TP_VL2_Fdbk  5013  [Keystone5013]  (value not drawn)
TP_VL3_Fdbk  5013  [Keystone5013]  (value not drawn)
U11  AMC1301DWVR  [DWV0008A]
U12  OPA320AIDBVR  [DBV0005A_N]
U13  OPA320AIDBVR  [DBV0005A_N]
U14  AMC1301DWVR  [DWV0008A]
U15  OPA320AIDBVR  [DBV0005A_N]
U16  DCH010505SN7  [EDJ0004A]
U17  AMC1301DWVR  [DWV0008A]
U18  OPA320AIDBVR  [DBV0005A_N]

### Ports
V_A (in), V_B (in), V_C (in), V_L1_Fdbk (out), V_L2_Fdbk (out), V_L3_Fdbk (out), V_N_Meas

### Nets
3.3V: C28.2 C29.2 C30.1 C32.1 C41.2 C42.1 C43.2 C51.2 C52.2 C56.1 R58.2 U11.8(VDD2) U12.5(V+) U13.5(V+) U14.8(VDD2) U15.5(V+) U17.8(VDD2) U18.5(V+)
5V: C53.1 L7.1
5V_N2: C27.2 C40.1 C50.2 C54.1 C55.1 L8.2 U11.1(VDD1) U14.1(VDD1) U17.1(VDD1)
GND: C28.1 C29.1 C30.2 C32.2 C33.2 C34.2 C36.1 C37.2 C38.1 C41.1 C42.2 C43.1 C45.1 C46.2 C48.1 C51.1 C52.1 C53.2 C56.2 C58.2 C59.2 C61.2 R60.1 TP_GND2.1 U11.5(GND2) U12.2(V-) U13.2(V-) U14.5(GND2) U15.2(V-) U16.2(-VI) U17.5(GND2) U18.2(V-)
1.65V: C36.2 C37.1 C48.2 C61.1 R57.1 R59.2 R72.1 R84.1
V_A: R46.2 ; port V_A
V_B: R61.2 ; port V_B
V_C: R73.2 ; port V_C
V_L1_Fdbk: C33.1 R53.2 TP_VL1_Fdbk.1 ; port V_L1_Fdbk
V_L2_Fdbk: C45.2 R68.2 TP_VL2_Fdbk.1 ; port V_L2_Fdbk
V_L3_Fdbk: C58.1 R80.2 TP_VL3_Fdbk.1 ; port V_L3_Fdbk
V_N_Meas: C27.1 C35.1 C40.2 C47.1 C50.1 C54.2 C55.2 C60.1 R52.1 R56.2 R67.1 R71.2 R79.1 R83.2 U11.4(GND1) U14.4(GND1) U16.5(-VO) U17.4(GND1) ; port V_N_Meas
NetC26_1: C26.1 R48.1 R51.2 U12.4(IN-)
NetC26_2: C26.2 R48.2 R53.1 U12.1(OUT)
NetC31_1: C31.1 R50.2 R51.1
NetC31_2: C31.2 R54.2 R55.1
NetC34_1: C34.1 R55.2 R57.2 U12.3(IN+)
NetC35_2: C35.2 R56.1 U11.3(VINN)
NetC38_2: C38.2 R58.1 R60.2 U13.3(IN+)
NetC39_1: C39.1 R63.1 R66.2 U15.4(IN-)
NetC39_2: C39.2 R63.2 R68.1 U15.1(OUT)
NetC44_1: C44.1 R65.2 R66.1
NetC44_2: C44.2 R69.2 R70.1
NetC46_1: C46.1 R70.2 R72.2 U15.3(IN+)
NetC47_2: C47.2 R71.1 U14.3(VINN)
NetC49_1: C49.1 R75.1 R78.2 U18.4(IN-)
NetC49_2: C49.2 R75.2 R80.1 U18.1(OUT)
NetC57_1: C57.1 R77.2 R78.1
NetC57_2: C57.2 R81.2 R82.1
NetC59_1: C59.1 R82.2 R84.2 U18.3(IN+)
NetC60_2: C60.2 R83.1 U17.3(VINN)
NetL7_2: L7.2 U16.1(+VI)
NetL8_1: L8.1 U16.7(+VO)
NetR46_1: R46.1 R47.2
NetR47_1: R47.1 R49.2
NetR49_1: R49.1 R52.2 U11.2(VINP)
NetR50_1: R50.1 U11.6(VOUTN)
NetR54_1: R54.1 U11.7(VOUTP)
NetR59_1: R59.1 U13.1(OUT) U13.4(IN-)
NetR61_1: R61.1 R62.2
NetR62_1: R62.1 R64.2
NetR64_1: R64.1 R67.2 U14.2(VINP)
NetR65_1: R65.1 U14.6(VOUTN)
NetR69_1: R69.1 U14.7(VOUTP)
NetR73_1: R73.1 R74.2
NetR74_1: R74.1 R76.2
NetR76_1: R76.1 R79.2 U17.2(VINP)
NetR77_1: R77.1 U17.6(VOUTN)
NetR81_1: R81.1 U17.7(VOUTP)

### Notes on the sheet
- High Voltage
- AC Input Voltage Sensing
- (near R61) High Voltage
- (near R73) High Voltage

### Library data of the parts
C26 C31 C34 C35 C39 C44 C46 C47 C49 C57 C59 C60 = C0603C181J5GACTU: CAP, CERM, 180 pF, 50 V, +/- 5%, C0G/NP0, 0603; Manufacturer: Kemet; Polarized: N; CompType: Capacitor; Value: 180pF; U/M: EA; Cap_F: 0.00000000018; Tolerance_%: 5; Value1: Unknown; VDC_V: 50; Value2: 50V; TaMin_C: -55; TaMax_C: 125; SizeArea_mm2: 1.28; SizeAreaWB_mm2: 4.68; SizeX_mm: 1.6; SizeY_mm: 0.8; SizeZ_mm: 1; AEC Category: Q200
C27 C29 C30 C32 C33 C36-C38 C40 C42 C43 C45 C48 C50 C52 C56 C58 C61 = 0603YC104JAT2A: as C69 on sheet MCU011A_SensingInductorCurrent
C28 C41 C51 = C2012X5R1H475K125AB: CAP, CERM, 4.7 µF, 50 V, +/- 10%, X5R, 0805; Manufacturer: TDK; Polarized: N; CompType: Capacitor; Value: 4.7uF; U/M: EA; Cap_F: 0.0000047; Tolerance_%: 10; Value1: Unknown; VDC_V: 50; Value2: 50V; TaMin_C: -55; TaMax_C: 85; AEC Category: Q200
C53 C54 = GRM21BR71H105KA12L: as C64 on sheet MCU011A_SensingInductorCurrent
C55 = C0805C104K3RACTU: as C63 on sheet MCU011A_SensingInductorCurrent
L7 L8 = MPZ2012S300AT000: as L9-L18 on sheet MCU011A_SensingInductorCurrent
R46 R47 R49 R61 R62 R64 R73 R74 R76 = CRCW08051M00JNEA: RES, 1.0 M, 5%, 0.125 W, 0805; Manufacturer: Vishay-Dale; CompType: Resistor; Value: 1.0Meg; Res_ohm: 1000000; Value_Code: 1M00; Tolerance_%: 5; Power_W: 0.125; Value2: 0.125W; VDC_V: 150; TempCo: 200 ppm/C; EIA_Code: E24; U/M: EA; AEC Category: Q200
R48 R63 R75 = ERJ-3EKF7501V: RES, 7.50 k, 1%, 0.1 W, 0603; Manufacturer: Panasonic; CompType: Resistor; Value: 7.50k; Res_ohm: 7500; Value_Code: 7k50; Tolerance_%: 1; Power_W: 0.1; Value2: 0.1W; VDC_V: 75; TempCo: 100 ppm/C; EIA_Code: E96; U/M: EA; AEC Category: Q200
R50 R51 R54 R55 R65 R66 R69 R70 R77 R78 R81 R82 = RC0603FR-074K7L: RES, 4.70 k, 1%, 0.1 W, 0603; Manufacturer: Yageo America; CompType: Resistor; Value: 4.70k; Res_ohm: 4700; Value_Code: 4k70; Tolerance_%: 1; Power_W: 0.1; Value2: 0.1W; VDC_V: 150; TempCo: 200 ppm/C; U/M: EA; AEC Category: Q200
R52 R56 R67 R71 R79 R83 = CRCW06032K00FKEA: RES, 2.00 k, 1%, 0.1 W, 0603; Manufacturer: Vishay-Dale; CompType: Resistor; Value: 2.00k; Res_ohm: 2000; Value_Code: 2k00; Tolerance_%: 1; Power_W: 0.1; Value2: 0.1W; VDC_V: 75; TempCo: 100 ppm/C; SizeArea_mm2: 1.28; SizeX_mm: 1.6; SizeY_mm: 0.8; EIA_Code: E96; U/M: EA; AEC Category: Q200
R53 R68 R80 = CRCW060368R1FKEA: as R87 on sheet MCU011A_SensingInductorCurrent
R57 R72 R84 = ERJ-3EKF7501V: RES, 7.50 k, 1%, 0.1 W, 0603; Manufacturer: Panasonic; CompType: Resistor; Value: 7.50k; Res_ohm: 7500; Value_Code: 7k50; Tolerance_%: 1; Power_W: 0.1; Value2: 0.1W; VDC_V: 75; TempCo: 100 ppm/C; EIA_Code: E96; U/M: EA; AEC Category: Q200; SizeArea_mm2: 1.28; SizeX_mm: 1.6; SizeY_mm: 0.8
R58 R60 = CRCW060310K0FKEA: RES, 10.0 k, 1%, 0.1 W, 0603; Manufacturer: Vishay-Dale; CompType: Resistor; Value: 10.0k; Res_ohm: 10000; Value_Code: 10k0; Tolerance_%: 1; Power_W: 0.1; Value2: 0.1W; VDC_V: 75; TempCo: 100 ppm/C; SizeArea_mm2: 1.28; SizeX_mm: 1.6; SizeY_mm: 0.8; EIA_Code: E96; U/M: EA; AEC Category: Q200
R59 = CRCW060310R0FKEA: RES, 10.0, 1%, 0.1 W, 0603; Manufacturer: Vishay-Dale; CompType: Resistor; Value: 10.0; Res_ohm: 10; Value_Code: 10R0; Tolerance_%: 1; Power_W: 0.1; Value2: 0.1W; VDC_V: 75; TempCo: 100 ppm/C; SizeArea_mm2: 1.28; SizeX_mm: 1.6; SizeY_mm: 0.8; EIA_Code: E96; U/M: EA; AEC Category: Q200
TP_GND2 = 5128: as TP_GND3 on sheet MCU011A_SensingInductorCurrent
TP_VL1_Fdbk TP_VL2_Fdbk TP_VL3_Fdbk = 5013: as TP_IL1 on sheet MCU011A_SensingInductorCurrent
U11 U14 U17 = AMC1301DWVR: Precision +/-250-mV Input, 3-us Delay, Reinforced Isolated Amplifier, DWV0008A (SOIC-8); Manufacturer: Texas Instruments; SymbolCreator: Altium; SizeArea_mm2: 67.275; SizeAreaWB_mm2: 105.975; SizeX_mm: 11.5; SizeY_mm: 5.85; SizeZ_mm: 2.8; CompType: IC; U/M: EA
U12 U13 U15 U18 = OPA320AIDBVR: Precision, 20 MHz, 0.9 pA Ib, RRIO, CMOS Operational Amplifier, 1.8 to 5.5 V, -40 to 125 degC, 5-pin SOT23 (DBV0005A), Green (RoHS & no Sb/Br); Manufacturer: Texas Instruments; Alternate PartNumber: Equivalent; CMRR(Min)(dB): 100; IIB(Max)(pA): 0.9; Iq per channel(Max)(mA): 1.75; Number of Channels: 2; Offset Drift(Typ)(uV/C): 1.5; Slew Rate(Typ)(V/us): 10; Sub Family: High Output Current Amplifier (>=50mA), Low Input Bias Current Amp (<=10pA), Low Noise Amp (<=10nV/rtHz), Low Offset Voltage Amplifier (<=500uV), Low Supply Voltage Amplifier (<=2.7V), Precision Amplifier; Total Supply Voltage(Max)(+5V is 5, +/-5V is 10): 5.5; Total Supply Voltage(Min)(+5V is 5, +/-5V is 10): 1.8; Vio (25C)(Max)(mV): 0.15; Vn at 1kHz(Typ)(nV/rtHz): 8.5
U16 = DCH010505SN7: as U20 on sheet MCU011A_SensingInductorCurrent

## Sheet MCU011A_SensingOutputVoltage.SchDoc: Output DC Bus Voltage Sensing
size 431 x 279 mm; Date: Not shown in title block; ApprovedBy: Not shown in title block; CheckedBy: Not shown in title block; Author: Not shown in title block; CompanyName: Not shown in title block; Engineer: Not shown in title block; Organization: Not shown in title block; Address1: Not shown in title block; Address2: Not shown in title block; Address3: Not shown in title block; Address4: Not shown in title block; DocumentNumber: 1; Revision: Use project parameter SCH_Rev; SheetNumber: 7; SheetTotal: 10; PageSetup: Record=PageOptions¦CenterHorizontal=True¦CenterVertical=True¦PrintScale=1.00¦XCorrection=1.00¦YCorrection=1.00¦PrintKind=0¦BorderSize=5000000¦LeftOffset=0¦BottomOffset=0¦Orientation=2¦PaperLength=1000¦PaperWidth=1000¦Scale=100¦PaperSource=15¦PrintQuality=600¦MediaType=1¦DitherType=10¦PaperKind=Letter¦PrintScaleMode=1
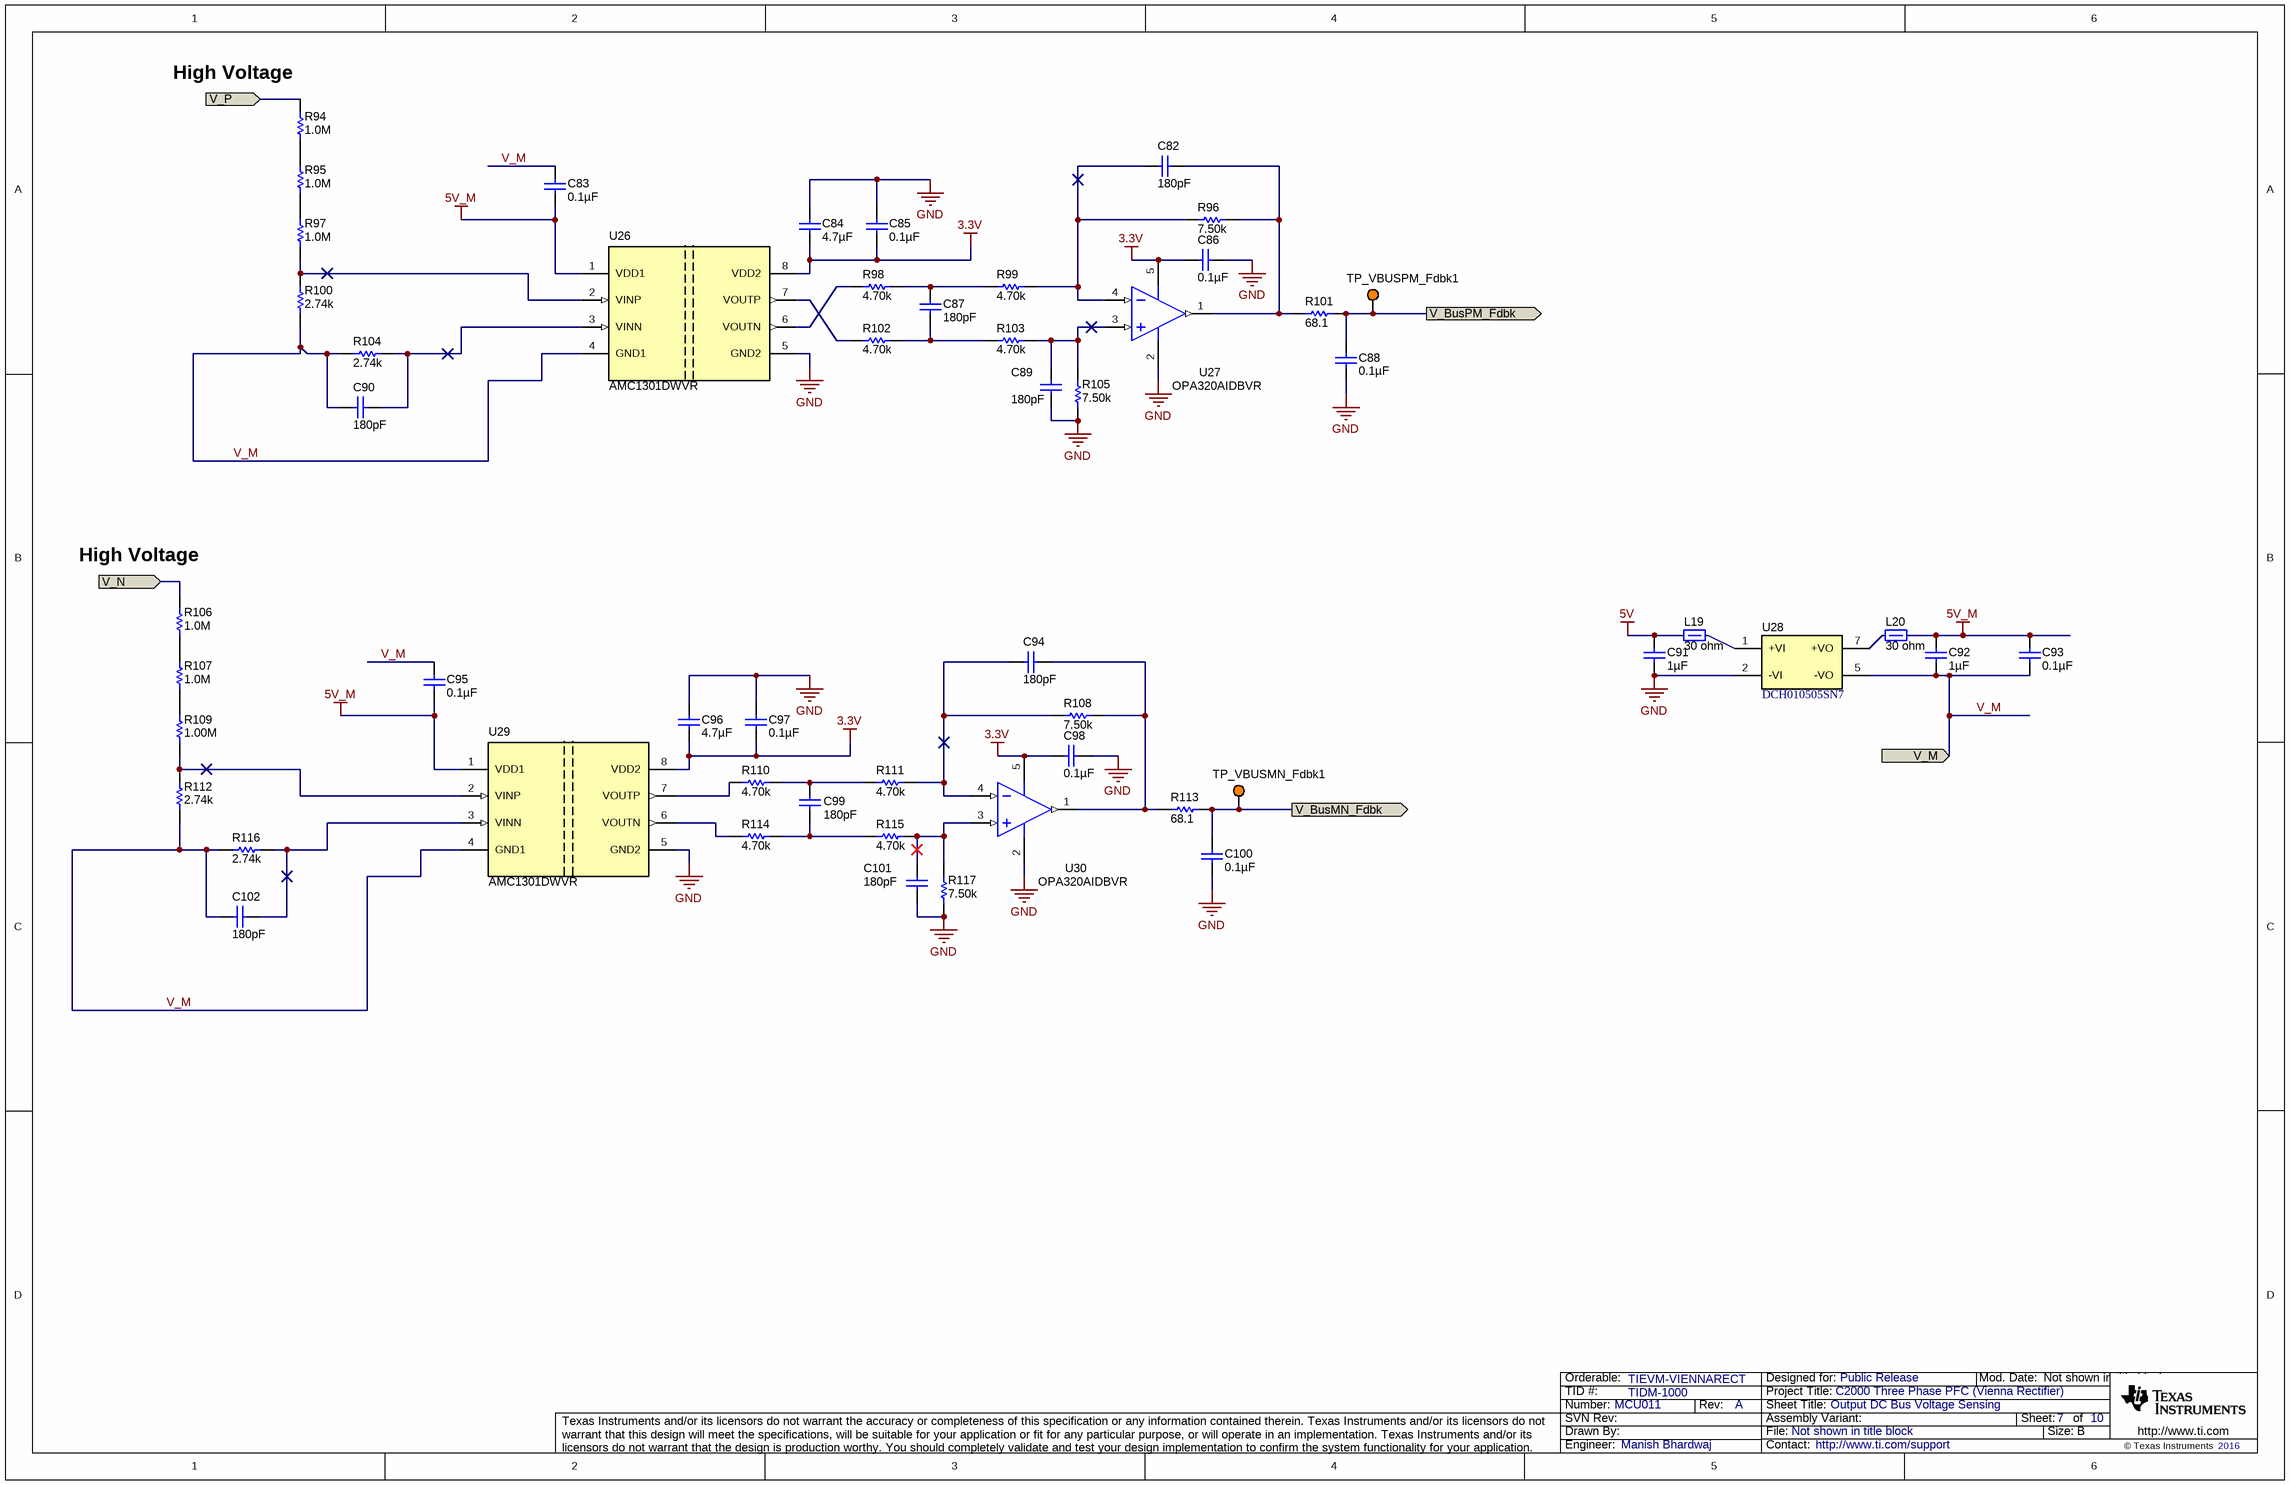
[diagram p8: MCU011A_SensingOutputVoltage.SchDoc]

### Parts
C82  ValueDisplayed: 180pF  [0603]  (hidden comment: C0603C181J5GACTU)
C83  ValueDisplayed: 0.1µF  [0603]  (hidden comment: 0603YC104JAT2A)
C84  ValueDisplayed: 4.7µF  [0805_HV]  (hidden comment: C2012X5R1H475K125AB)
C85  ValueDisplayed: 0.1µF  [0603]  (hidden comment: 0603YC104JAT2A)
C86  ValueDisplayed: 0.1µF  [0603]  (hidden comment: 0603YC104JAT2A)
C87  ValueDisplayed: 180pF  [0603]  (hidden comment: C0603C181J5GACTU)
C88  ValueDisplayed: 0.1µF  [0603]  (hidden comment: 0603YC104JAT2A)
C89  ValueDisplayed: 180pF  [0603]  (hidden comment: C0603C181J5GACTU)
C90  ValueDisplayed: 180pF  [0603]  (hidden comment: C0603C181J5GACTU)
C91  ValueDisplayed: 1µF  [0805]  (hidden comment: GRM21BR71H105KA12L)
C92  ValueDisplayed: 1µF  [0805]  (hidden comment: GRM21BR71H105KA12L)
C93  ValueDisplayed: 0.1µF  [0805]  (hidden comment: C0805C104K3RACTU)
C94  ValueDisplayed: 180pF  [0603]  (hidden comment: C0603C181J5GACTU)
C95  ValueDisplayed: 0.1µF  [0603]  (hidden comment: 0603YC104JAT2A)
C96  ValueDisplayed: 4.7µF  [0805_HV]  (hidden comment: C2012X5R1H475K125AB)
C97  ValueDisplayed: 0.1µF  [0603]  (hidden comment: 0603YC104JAT2A)
C98  ValueDisplayed: 0.1µF  [0603]  (hidden comment: 0603YC104JAT2A)
C99  ValueDisplayed: 180pF  [0603]  (hidden comment: C0603C181J5GACTU)
C100  ValueDisplayed: 0.1µF  [0603]  (hidden comment: 0603YC104JAT2A)
C101  ValueDisplayed: 180pF  [0603]  (hidden comment: C0603C181J5GACTU)
C102  ValueDisplayed: 180pF  [0603]  (hidden comment: C0603C181J5GACTU)
L19  value 30 ohm  [0805]  (hidden comment: MPZ2012S300AT000)
L20  value 30 ohm  [0805]  (hidden comment: MPZ2012S300AT000)
R94  ValueDisplayed: 1.0M  [0805_HV]  (hidden comment: CRCW08051M00JNEA)
R95  ValueDisplayed: 1.0M  [0805_HV]  (hidden comment: CRCW08051M00JNEA)
R96  ValueDisplayed: 7.50k  [0603]  (hidden comment: ERJ-3EKF7501V)
R97  ValueDisplayed: 1.0M  [0805_HV]  (hidden comment: CRCW08051M00JNEA)
R98  ValueDisplayed: 4.70k  [0603]  (hidden comment: RC0603FR-074K7L)
R99  ValueDisplayed: 4.70k  [0603]  (hidden comment: RC0603FR-074K7L)
R100  ValueDisplayed: 2.74k  [0603]  (hidden comment: CRCW06032K74FKEA)
R101  ValueDisplayed: 68.1  [0603]  (hidden comment: CRCW060368R1FKEA)
R102  ValueDisplayed: 4.70k  [0603]  (hidden comment: RC0603FR-074K7L)
R103  ValueDisplayed: 4.70k  [0603]  (hidden comment: RC0603FR-074K7L)
R104  ValueDisplayed: 2.74k  [0603]  (hidden comment: CRCW06032K74FKEA)
R105  ValueDisplayed: 7.50k  [0603]  (hidden comment: ERJ-3EKF7501V)
R106  ValueDisplayed: 1.0M  [0805_HV]  (hidden comment: CRCW08051M00JNEA)
R107  ValueDisplayed: 1.0M  [0805_HV]  (hidden comment: CRCW08051M00JNEA)
R108  ValueDisplayed: 7.50k  [0603]  (hidden comment: ERJ-3EKF7501V)
R109  ValueDisplayed: 1.00M  [0805_HV]  (hidden comment: RT0805BRD071ML)
R110  ValueDisplayed: 4.70k  [0603]  (hidden comment: RC0603FR-074K7L)
R111  ValueDisplayed: 4.70k  [0603]  (hidden comment: RC0603FR-074K7L)
R112  ValueDisplayed: 2.74k  [0603]  (hidden comment: CRCW06032K74FKEA)
R113  ValueDisplayed: 68.1  [0603]  (hidden comment: CRCW060368R1FKEA)
R114  ValueDisplayed: 4.70k  [0603]  (hidden comment: RC0603FR-074K7L)
R115  ValueDisplayed: 4.70k  [0603]  (hidden comment: RC0603FR-074K7L)
R116  ValueDisplayed: 2.74k  [0603]  (hidden comment: CRCW06032K74FKEA)
R117  ValueDisplayed: 7.50k  [0603]  (hidden comment: ERJ-3EKF7501V)
TP_VBUSMN_Fdbk1  5013  [Keystone5013]  (value not drawn)
TP_VBUSPM_Fdbk1  5013  [Keystone5013]  (value not drawn)
U26  AMC1301DWVR  [DWV0008A]
U27  OPA320AIDBVR  [DBV0005A_N]
U28  DCH010505SN7  [EDJ0004A]
U29  AMC1301DWVR  [DWV0008A]
U30  OPA320AIDBVR  [DBV0005A_N]

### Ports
V_BusMN_Fdbk (out), V_BusPM_Fdbk (out), V_M, V_N (in), V_P (in)

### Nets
3.3V: C84.2 C85.1 C86.1 C96.2 C97.2 C98.1 U26.8(VDD2) U27.5(V+) U29.8(VDD2) U30.5(V+)
5V: C91.1 L19.1
5V_M: C83.1 C92.1 C93.1 C95.1 L20.2 U26.1(VDD1) U29.1(VDD1)
GND: C84.1 C85.2 C86.2 C88.1 C89.2 C91.2 C96.1 C97.1 C98.2 C100.2 C101.2 R105.1 R117.1 U26.5(GND2) U27.2(V-) U28.2(-VI) U29.5(GND2) U30.2(V-)
V_BusMN_Fdbk: C100.1 R113.2 TP_VBUSMN_Fdbk1.1 ; port V_BusMN_Fdbk
V_BusPM_Fdbk: C88.2 R101.2 TP_VBUSPM_Fdbk1.1 ; port V_BusPM_Fdbk
V_M: C83.2 C90.1 C92.2 C93.2 C95.2 C102.1 R100.1 R104.2 R112.1 R116.2 U26.4(GND1) U28.5(-VO) U29.4(GND1) ; port V_M
VBUSN: R106.2 ; port V_N
VBUSP: R94.2 ; port V_P
NetC82_1: C82.1 R96.1 R99.2 U27.4(IN-)
NetC82_2: C82.2 R96.2 R101.1 U27.1(OUT)
NetC87_1: C87.1 R98.2 R99.1
NetC87_2: C87.2 R102.2 R103.1
NetC89_1: C89.1 R103.2 R105.2 U27.3(IN+)
NetC90_2: C90.2 R104.1 U26.3(VINN)
NetC94_1: C94.1 R108.1 R111.2 U30.4(IN-)
NetC94_2: C94.2 R108.2 R113.1 U30.1(OUT)
NetC99_1: C99.1 R110.2 R111.1
NetC99_2: C99.2 R114.2 R115.1
NetC101_1: C101.1 R115.2 R117.2 U30.3(IN+)
NetC102_2: C102.2 R116.1 U29.3(VINN)
NetL19_2: L19.2 U28.1(+VI)
NetL20_1: L20.1 U28.7(+VO)
NetR94_1: R94.1 R95.2
NetR95_1: R95.1 R97.2
NetR97_1: R97.1 R100.2 U26.2(VINP)
NetR98_1: R98.1 U26.6(VOUTN)
NetR102_1: R102.1 U26.7(VOUTP)
NetR106_1: R106.1 R107.2
NetR107_1: R107.1 R109.1
NetR109_2: R109.2 R112.2 U29.2(VINP)
NetR110_1: R110.1 U29.7(VOUTP)
NetR114_1: R114.1 U29.6(VOUTN)

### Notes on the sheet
- (near R94) High Voltage
- (near R106) High Voltage

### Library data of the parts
C82 C87 C89 C90 C94 C99 C101 C102 = C0603C181J5GACTU: as C26 on sheet MCU011A_SensingInputVoltage
C83 C85 C86 C88 C95 C97 C98 C100 = 0603YC104JAT2A: as C69 on sheet MCU011A_SensingInductorCurrent
C84 C96 = C2012X5R1H475K125AB: CAP, CERM, 4.7 µF, 50 V, +/- 10%, X5R, 0805; Manufacturer: TDK; Polarized: N; CompType: Capacitor; Value: 4.7uF; U/M: EA; Cap_F: 0.0000047; Tolerance_%: 10; Value1: Unknown; VDC_V: 50; Value2: 50V; TaMin_C: -55; TaMax_C: 85; Cap_Case: 0805; AEC Category: Q200
C91 C92 = GRM21BR71H105KA12L: as C64 on sheet MCU011A_SensingInductorCurrent
C93 = C0805C104K3RACTU: as C63 on sheet MCU011A_SensingInductorCurrent
L19 L20 = MPZ2012S300AT000: as L9-L18 on sheet MCU011A_SensingInductorCurrent
R94 R95 R97 R106 R107 = CRCW08051M00JNEA: as R46 on sheet MCU011A_SensingInputVoltage
R96 R108 = ERJ-3EKF7501V: as R48 on sheet MCU011A_SensingInputVoltage
R98 R99 R102 R103 R110 R111 R114 R115 = RC0603FR-074K7L: as R50 on sheet MCU011A_SensingInputVoltage
R100 R104 R112 R116 = CRCW06032K74FKEA: RES, 2.74 k, 1%, 0.1 W, 0603; Manufacturer: Vishay-Dale; CompType: Resistor; Value: 2.74k; Res_ohm: 2740; Value_Code: 2k74; Tolerance_%: 1; Power_W: 0.1; Value2: 0.1W; VDC_V: 75; TempCo: 100 ppm/C; SizeArea_mm2: 1.28; SizeX_mm: 1.6; SizeY_mm: 0.8; EIA_Code: E96; U/M: EA; AEC Category: Q200
R101 R113 = CRCW060368R1FKEA: as R87 on sheet MCU011A_SensingInductorCurrent
R105 R117 = ERJ-3EKF7501V: as R57 on sheet MCU011A_SensingInputVoltage
R109 = RT0805BRD071ML: RES, 1.00 M, 0.1%, 0.125 W, 0805; Manufacturer: Yageo America; CompType: Resistor; Value: 1.00Meg; Res_ohm: 1000000; Value_Code: 1M00; Tolerance_%: 0.1; Power_W: 0.125; Value2: 0.125W; VDC_V: 150; TempCo: 25 ppm/C; EIA_Code: E192; U/M: EA; AEC Category: Q200
TP_VBUSMN_Fdbk1 TP_VBUSPM_Fdbk1 = 5013: as TP_IL1 on sheet MCU011A_SensingInductorCurrent
U26 U29 = AMC1301DWVR: as U11 on sheet MCU011A_SensingInputVoltage
U27 U30 = OPA320AIDBVR: as U12 on sheet MCU011A_SensingInputVoltage
U28 = DCH010505SN7: as U20 on sheet MCU011A_SensingInductorCurrent

## Sheet MCU011A_Controller.SchDoc: Control Card Interface
size 431 x 279 mm; Date: Not shown in title block; ApprovedBy: Not shown in title block; CheckedBy: Not shown in title block; Author: Not shown in title block; CompanyName: Not shown in title block; DrawnBy: Manish Bhardwaj; Engineer: Not shown in title block; Organization: Not shown in title block; Address1: Not shown in title block; Address2: Not shown in title block; Address3: Not shown in title block; Address4: Not shown in title block; DocumentNumber: 1; Revision: Use project parameter SCH_Rev; SheetNumber: 8; SheetTotal: 10; PageSetup: Record=PageOptions¦CenterHorizontal=True¦CenterVertical=True¦PrintScale=1.00¦XCorrection=1.00¦YCorrection=1.00¦PrintKind=0¦BorderSize=5000000¦LeftOffset=0¦BottomOffset=0¦Orientation=2¦PaperLength=1000¦PaperWidth=1000¦Scale=100¦PaperSource=15¦PrintQuality=600¦MediaType=1¦DitherType=10¦PaperKind=Letter¦PrintScaleMode=1
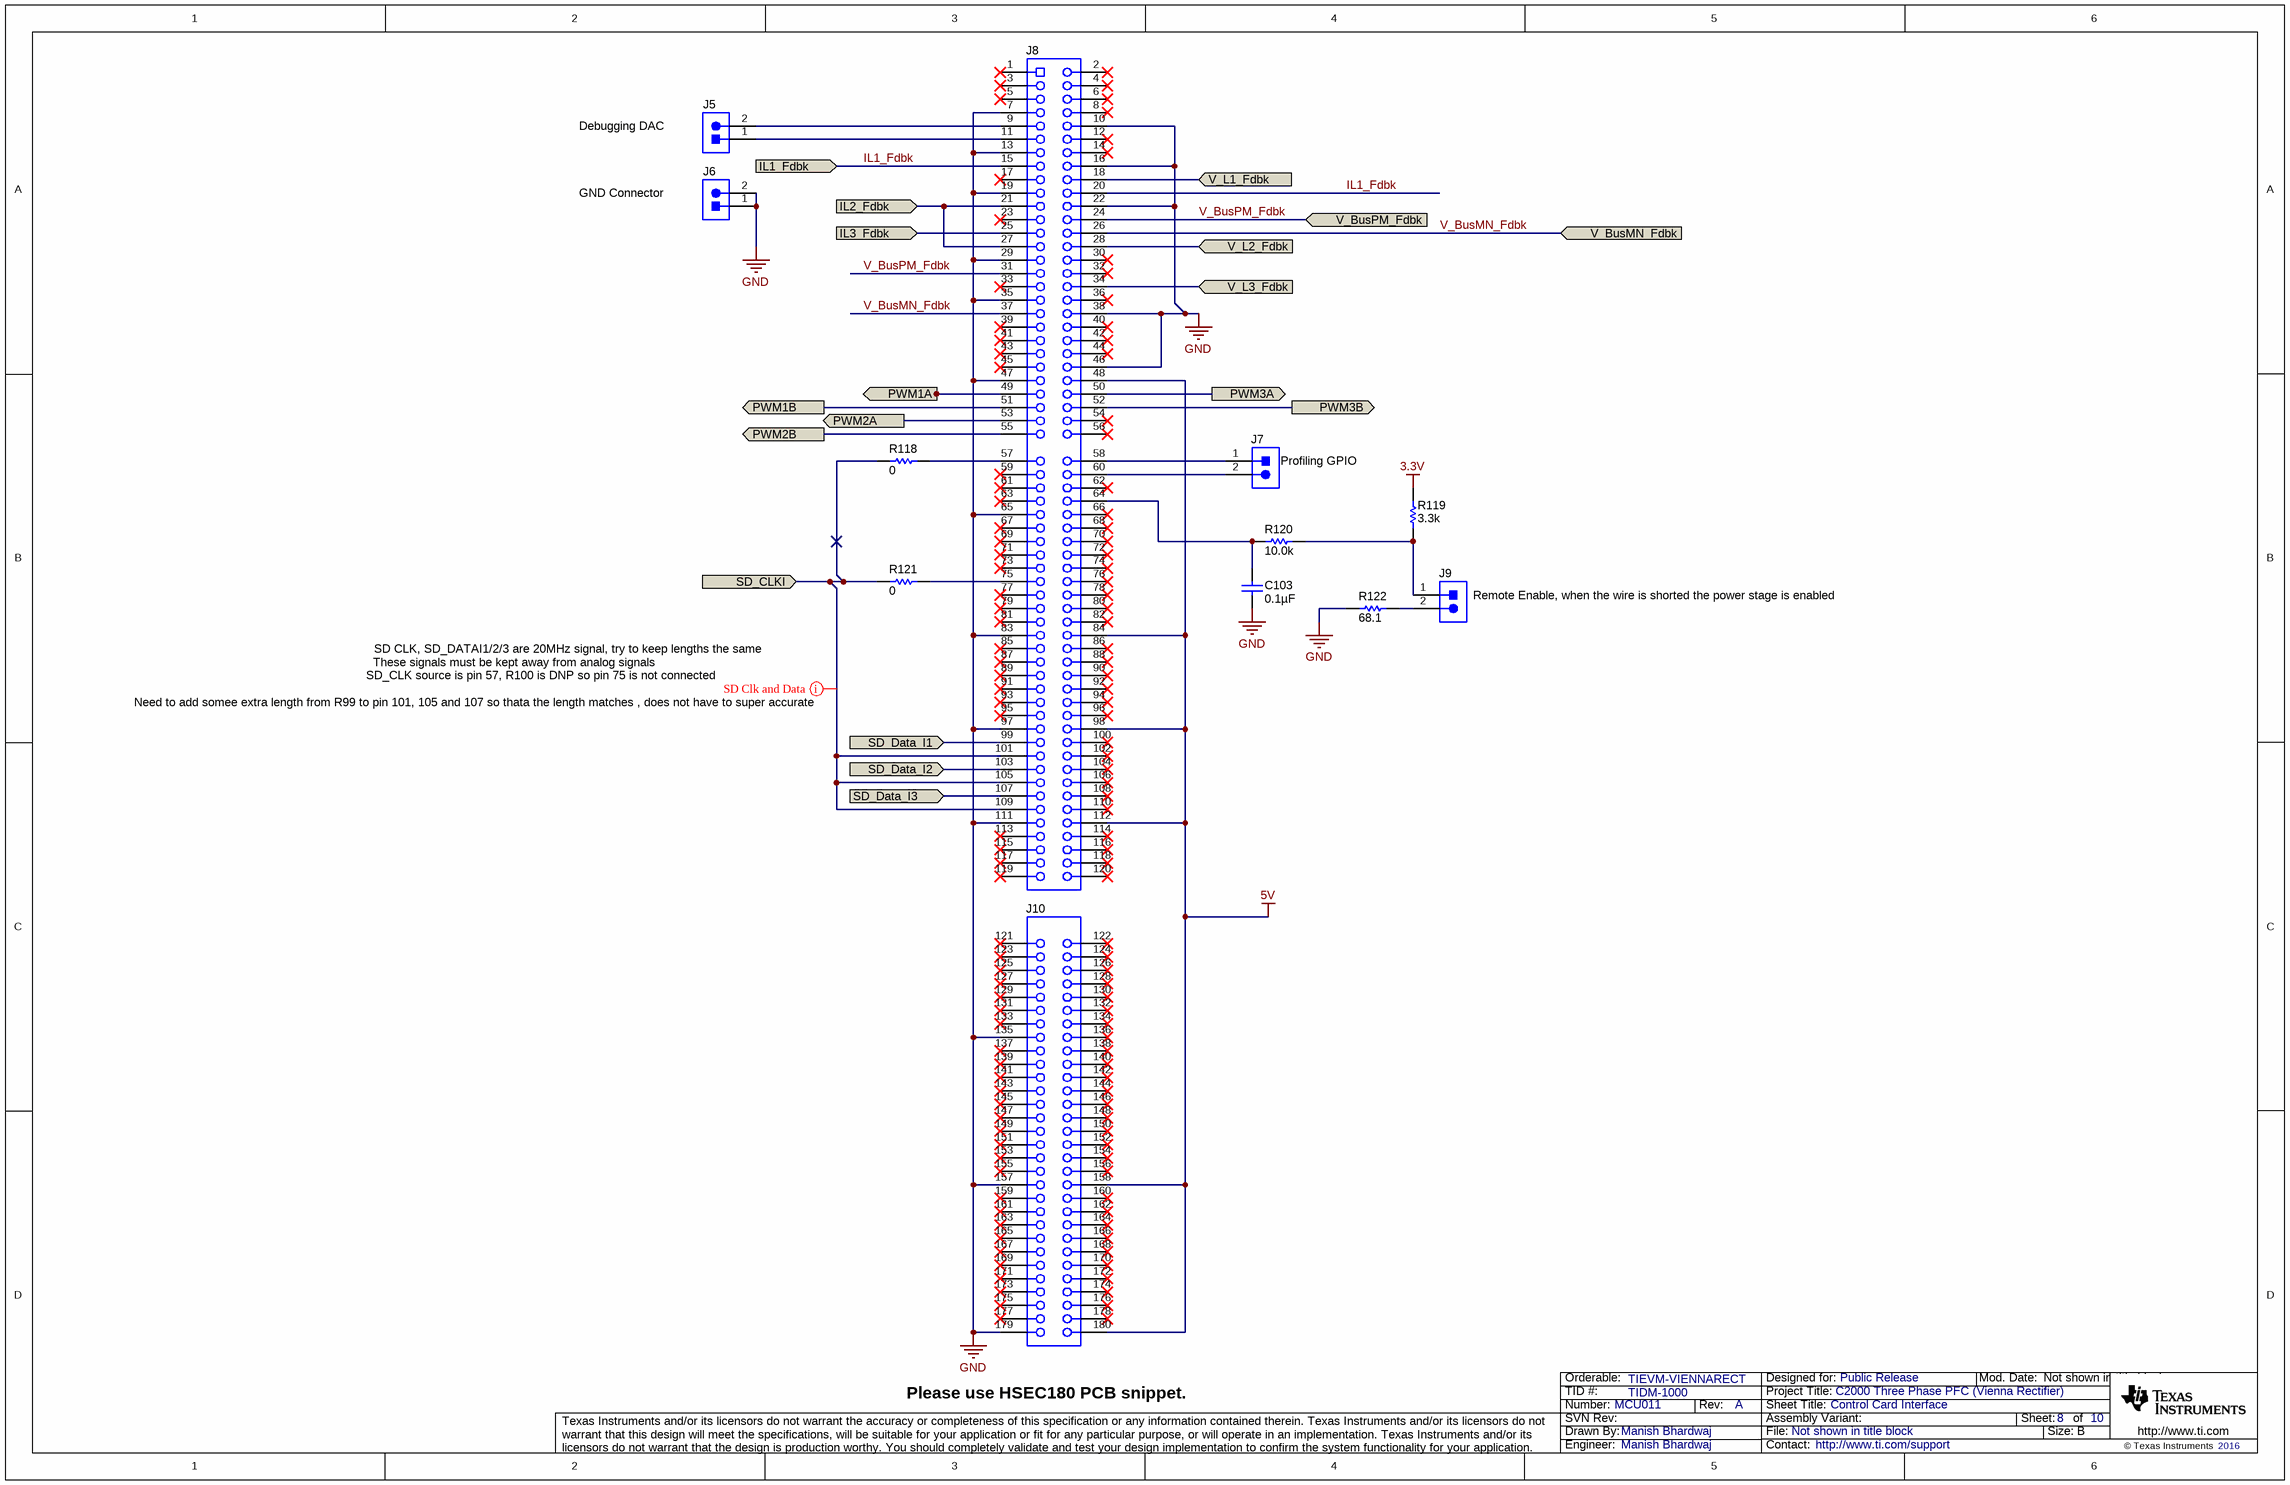
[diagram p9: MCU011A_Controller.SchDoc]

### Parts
C103  ValueDisplayed: 0.1µF  [0805]  (hidden comment: C0805C104K3RACTU)
J5  HTSW-102-07-G-S  [Samtec_HTSW-102-07-G-S]  (value not drawn)
J6  HTSW-102-07-G-S  [Samtec_HTSW-102-07-G-S]  (value not drawn)
J7  HTSW-102-07-G-S  [Samtec_HTSW-102-07-G-S]  (value not drawn)
J8  HSEC8-160-01-L-DV-A-BL  [controlCARD-120HSEC]  (value not drawn)
J9  HTSW-102-07-G-S  [Samtec_HTSW-102-07-G-S]  (value not drawn)
J10  HSEC8-130-01-L-DV-A  [controlCARD-180HSEC-60pinAddon]  (value not drawn)
R118  ValueDisplayed: 0  [0805]  (hidden comment: CRCW08050000Z0EA)
R119  ValueDisplayed: 3.3k  [0805]  (hidden comment: CRCW08053K30JNEA)
R120  ValueDisplayed: 10.0k  [0805]  (hidden comment: RT0805BRD0710KL)
R121  ValueDisplayed: 0  [0805]  (hidden comment: CRCW08050000Z0EA)
R122  ValueDisplayed: 68.1  [0603]  (hidden comment: CRCW060368R1FKEA)

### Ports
IL1_Fdbk (in), IL2_Fdbk (in), IL3_Fdbk (in), PWM1A (out), PWM1B (out), PWM2A (out), PWM2B (out), PWM3A (out), PWM3B (out), SD_CLKI (in), SD_Data_I1 (in), SD_Data_I2 (in), SD_Data_I3 (in), V_BusMN_Fdbk (in), V_BusPM_Fdbk (in), V_L1_Fdbk (in), V_L2_Fdbk (in), V_L3_Fdbk (in)

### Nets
3.3V: R119.2
5V: J8.48 J8.84 J8.98 J8.112 J10.158 J10.180
GND: C103.1 J6.1 J6.2 J8.7 J8.10 J8.13 J8.16 J8.19 J8.22 J8.29 J8.35 J8.38 J8.46 J8.47 J8.65 J8.83 J8.97 J8.111 J10.135 J10.157 J10.179 R122.1
IL1_Fdbk: J8.15 J8.20 ; port IL1_Fdbk
IL2_Fdbk: J8.21 J8.27 ; port IL2_Fdbk
IL3_Fdbk: J8.25 ; port IL3_Fdbk
PWM1A: J8.49 ; port PWM1A
PWM1B: J8.51 ; port PWM1B
PWM2A: J8.53 ; port PWM2A
PWM2B: J8.55 ; port PWM2B
PWM3A: J8.50 ; port PWM3A
PWM3B: J8.52 ; port PWM3B
SD_CLKI: J8.101 J8.105 J8.109 R118.2 R121.2 ; port SD_CLKI
SD_Data_I1: J8.99 ; port SD_Data_I1
SD_Data_I2: J8.103 ; port SD_Data_I2
SD_Data_I3: J8.107 ; port SD_Data_I3
V_BusMN_Fdbk: J8.26 J8.37 ; port V_BusMN_Fdbk
V_BusPM_Fdbk: J8.24 J8.31 ; port V_BusPM_Fdbk
V_L1_Fdbk: J8.18 ; port V_L1_Fdbk
V_L2_Fdbk: J8.28 ; port V_L2_Fdbk
V_L3_Fdbk: J8.34 ; port V_L3_Fdbk
NetC103_2: C103.2 J8.64 R120.2
NetJ5_1: J5.1 J8.11
NetJ5_2: J5.2 J8.9
NetJ7_1: J7.1 J8.58
NetJ7_2: J7.2 J8.60
NetJ8_57: J8.57 R118.1
NetJ8_75: J8.75 R121.1
NetJ9_1: J9.1 R119.1 R120.1
NetJ9_2: J9.2 R122.2

Not connected (* = marked no-connect by the designer): J8 1* 2* 3* 4* 5* 6* 8* 12* 14* 17* 23* 30* 32* 33* 36* 39* 40* 41* 42* 43* 44* 45* 54* 56* 59* 61* 62* 63* 66* 67* 68* 69* 70* 71* 72* 73* 74* 76* 77* 78* 79* 80* 81* 82* 85* 86* 87* 88* 89* 90* 91* 92* 93* 94* 95* 96* 100* 102* 104* 106* 108* 110* 113* 114* 115* 116* 117* 118* 119* 120*; J10 121* 122* 123* 124* 125* 126* 127* 128* 129* 130* 131* 132* 133* 134* 136* 137* 138* 139* 140* 141* 142* 143* 144* 145* 146* 147* 148* 149* 150* 151* 152* 153* 154* 155* 156* 159* 160* 161* 162* 163* 164* 165* 166* 167* 168* 169* 170* 171* 172* 173* 174* 175* 176* 177* 178*

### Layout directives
rule Undefined: SD_CLKI

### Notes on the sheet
- Debugging DAC
- GND Connector
- (near J7) Profiling GPIO
- (near J9) Remote Enable, when the wire is shorted the power stage is enabled
- Need to add somee extra length from R99 to pin 101, 105 and 107 so thata the length matches , does not have to super accurate
- These signals must be kept away from analog signals
- SD_CLK source is pin 57, R100 is DNP so pin 75 is not connected
- SD CLK, SD_DATAI1/2/3 are 20MHz signal, try to keep lengths the same
- (near J10) Please use HSEC180 PCB snippet.

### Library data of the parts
C103 = C0805C104K3RACTU: as C63 on sheet MCU011A_SensingInductorCurrent
J5-J7 J9 = HTSW-102-07-G-S: Header, 100mil, 2x1, Gold, TH; Manufacturer: Samtec; SymbolCreator: a0412235
J8 = controlCARD-120HSEC: C2000 controlCARD-120HSEC connector, SMT; Manufacturer: Samtec; SymbolCreator: a0412235; Note: The pin numbering does not match Samtec datasheet
J10 = controlCARD-180HSEC-60pinAddon: C2000 controlCARD-180HSEC (60-pin addon) connector, SMT; Manufacturer: Samtec; SymbolCreator: a0412235; Note: The pin numbering does not match Samtec datasheet
R118 R121 = CRCW08050000Z0EA: RES, 0, 5%, 0.125 W, 0805; Manufacturer: Vishay-Dale; CompType: Resistor; Value: 0; Value_Code: 0000; Tolerance_%: 5; Power_W: 0.125; Value2: 0.125W; VDC_V: 150; TempCo: 200 ppm/C; EIA_Code: E24; U/M: EA; AEC Category: Q200
R119 = CRCW08053K30JNEA: RES, 3.3 k, 5%, 0.125 W, 0805; Manufacturer: Vishay-Dale; CompType: Resistor; Value: 3.3k; Res_ohm: 3300; Value_Code: 3k30; Tolerance_%: 5; Power_W: 0.125; Value2: 0.125W; VDC_V: 150; TempCo: 200 ppm/C; EIA_Code: E24; U/M: EA; AEC Category: Q200
R120 = RT0805BRD0710KL: RES, 10.0 k, 0.1%, 0.125 W, 0805; Manufacturer: Yageo America; CompType: Resistor; Value: 10.0k; Res_ohm: 10000; Value_Code: 10k0; Tolerance_%: 0.1; Power_W: 0.125; Value2: 0.125W; VDC_V: 150; TempCo: 25 ppm/C; EIA_Code: E192; U/M: EA; AEC Category: Q200
R122 = CRCW060368R1FKEA: as R87 on sheet MCU011A_SensingInductorCurrent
